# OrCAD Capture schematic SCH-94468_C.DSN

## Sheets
1 COVER PAGE: title: SCH-94468; rev: C; company: NXP Semiconductor; note: SCH-94468 PDF: SPF-94468; note: 6501 William Cannon Drive West; note: Austin, TX 78735-8598
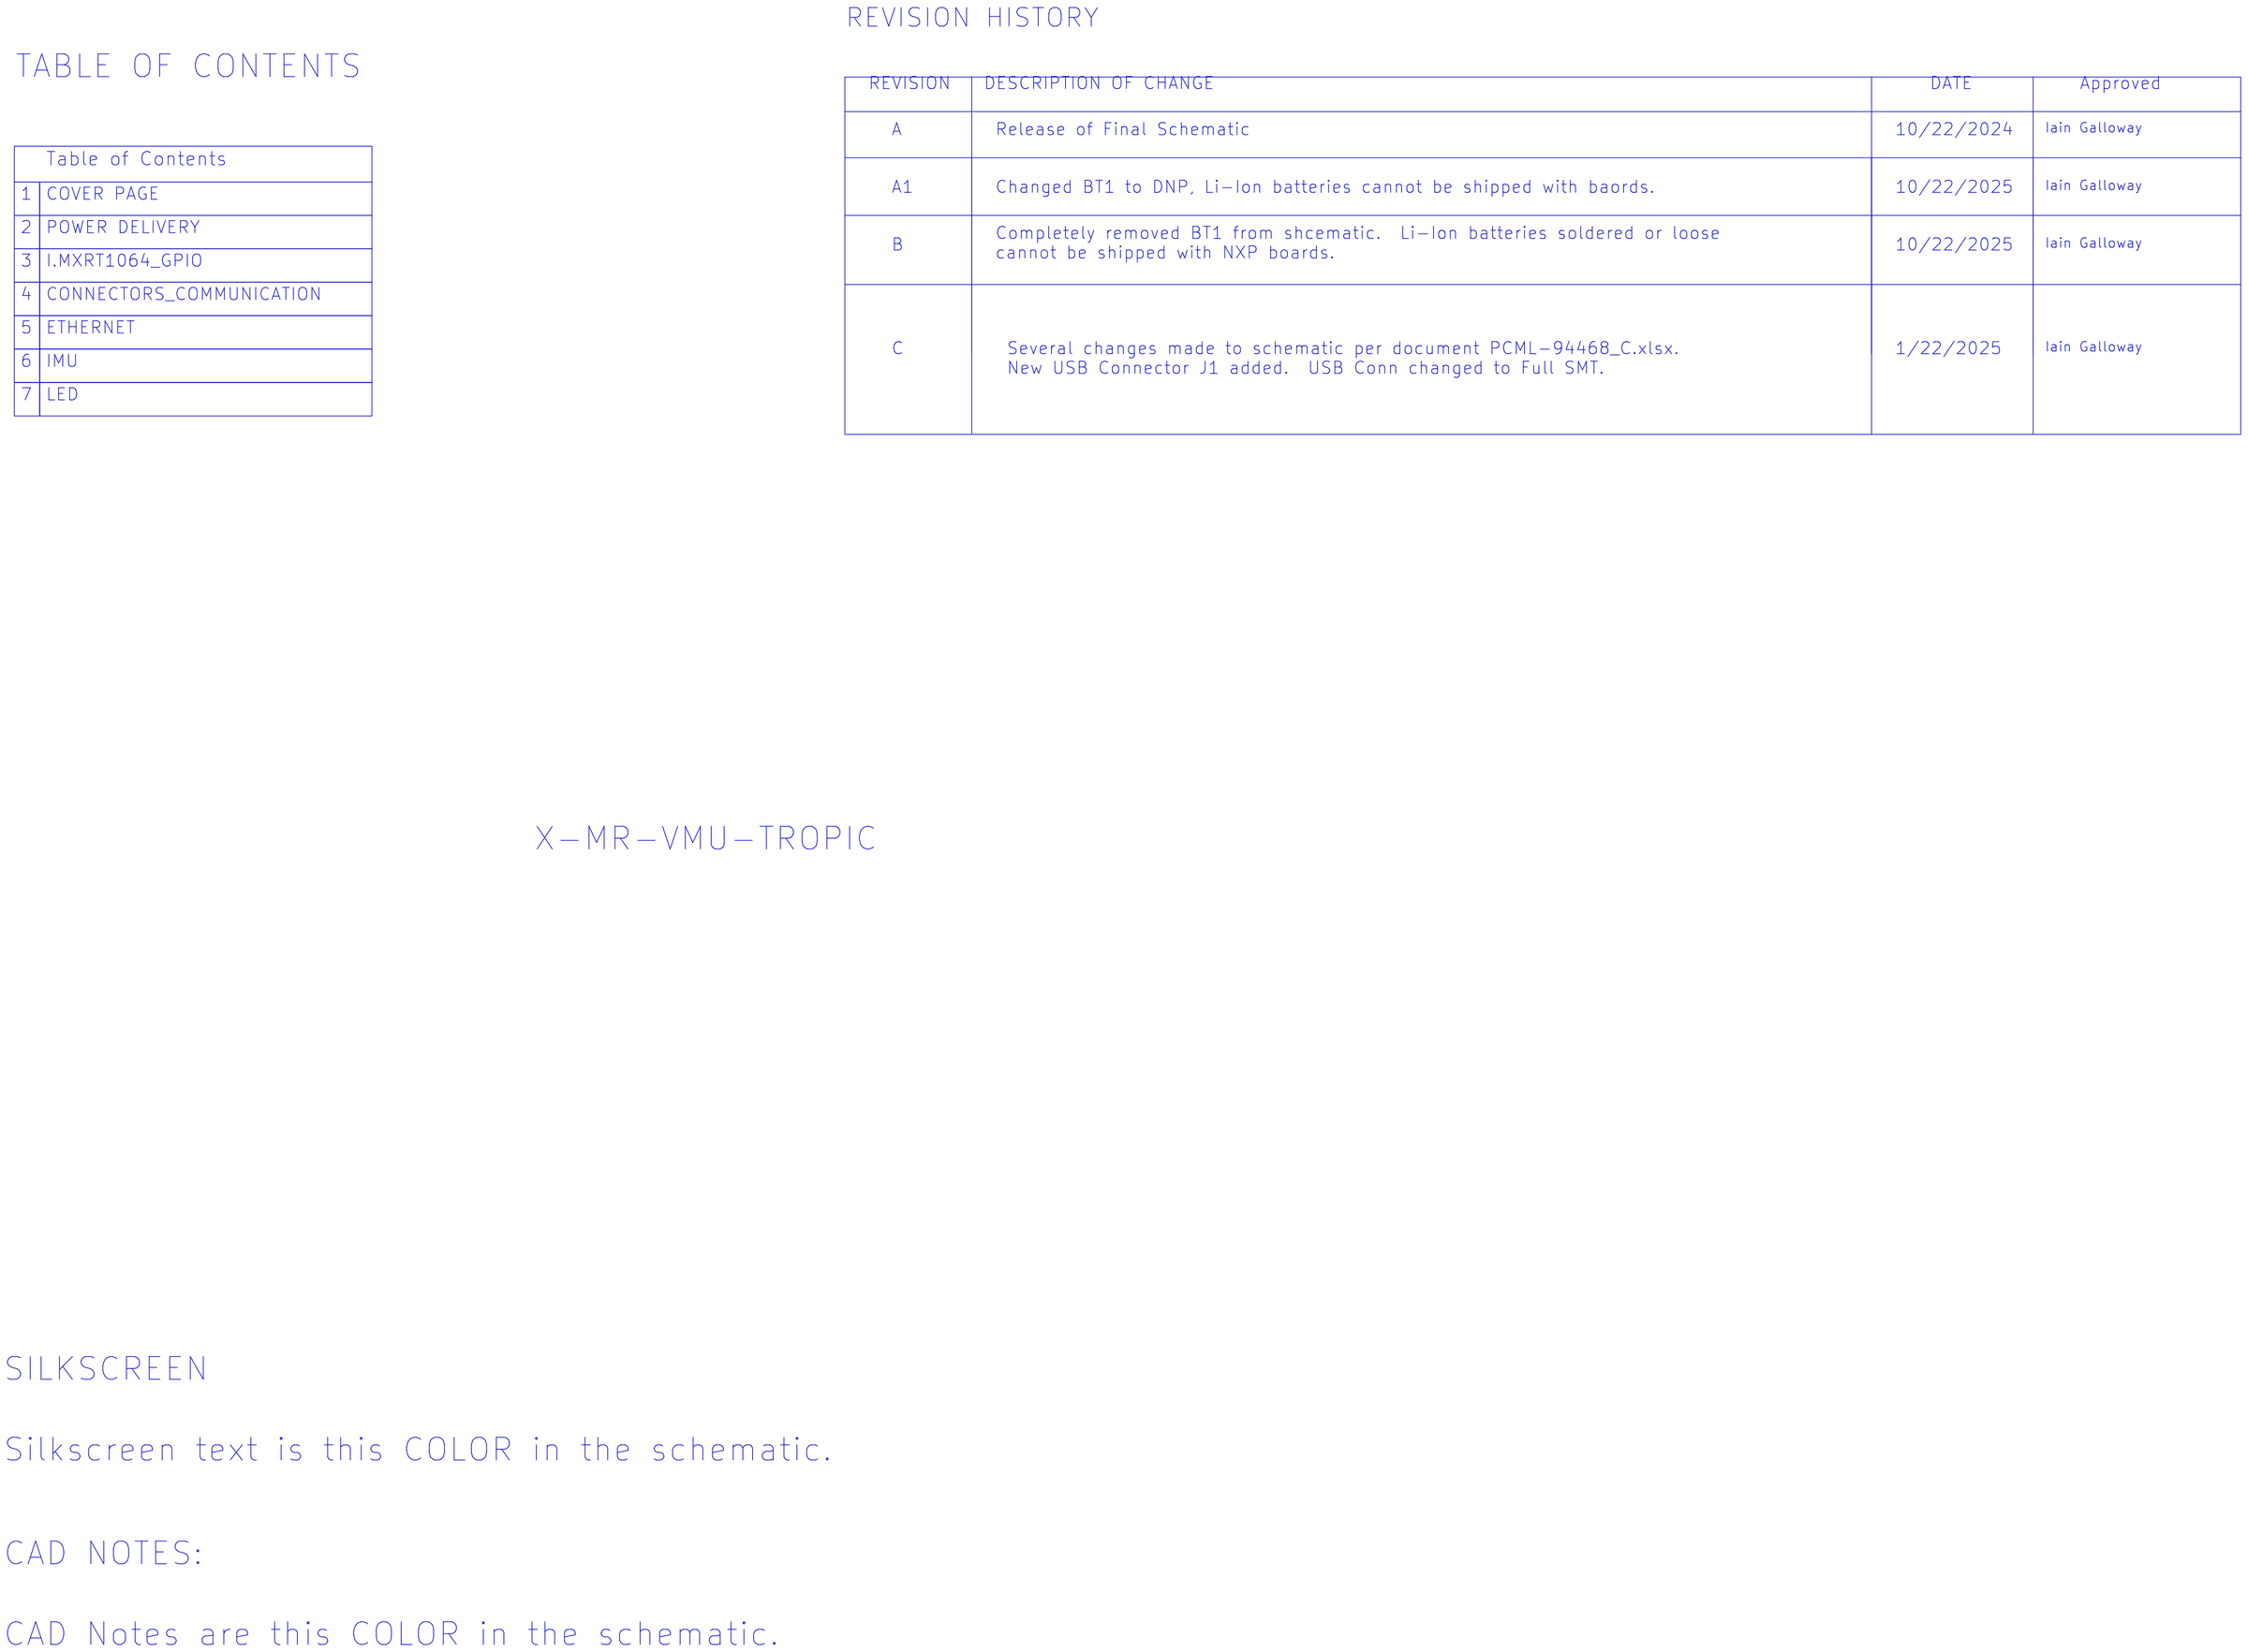
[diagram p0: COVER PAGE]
2 POWER DELIVERY: size C; company: NXP Semiconductors
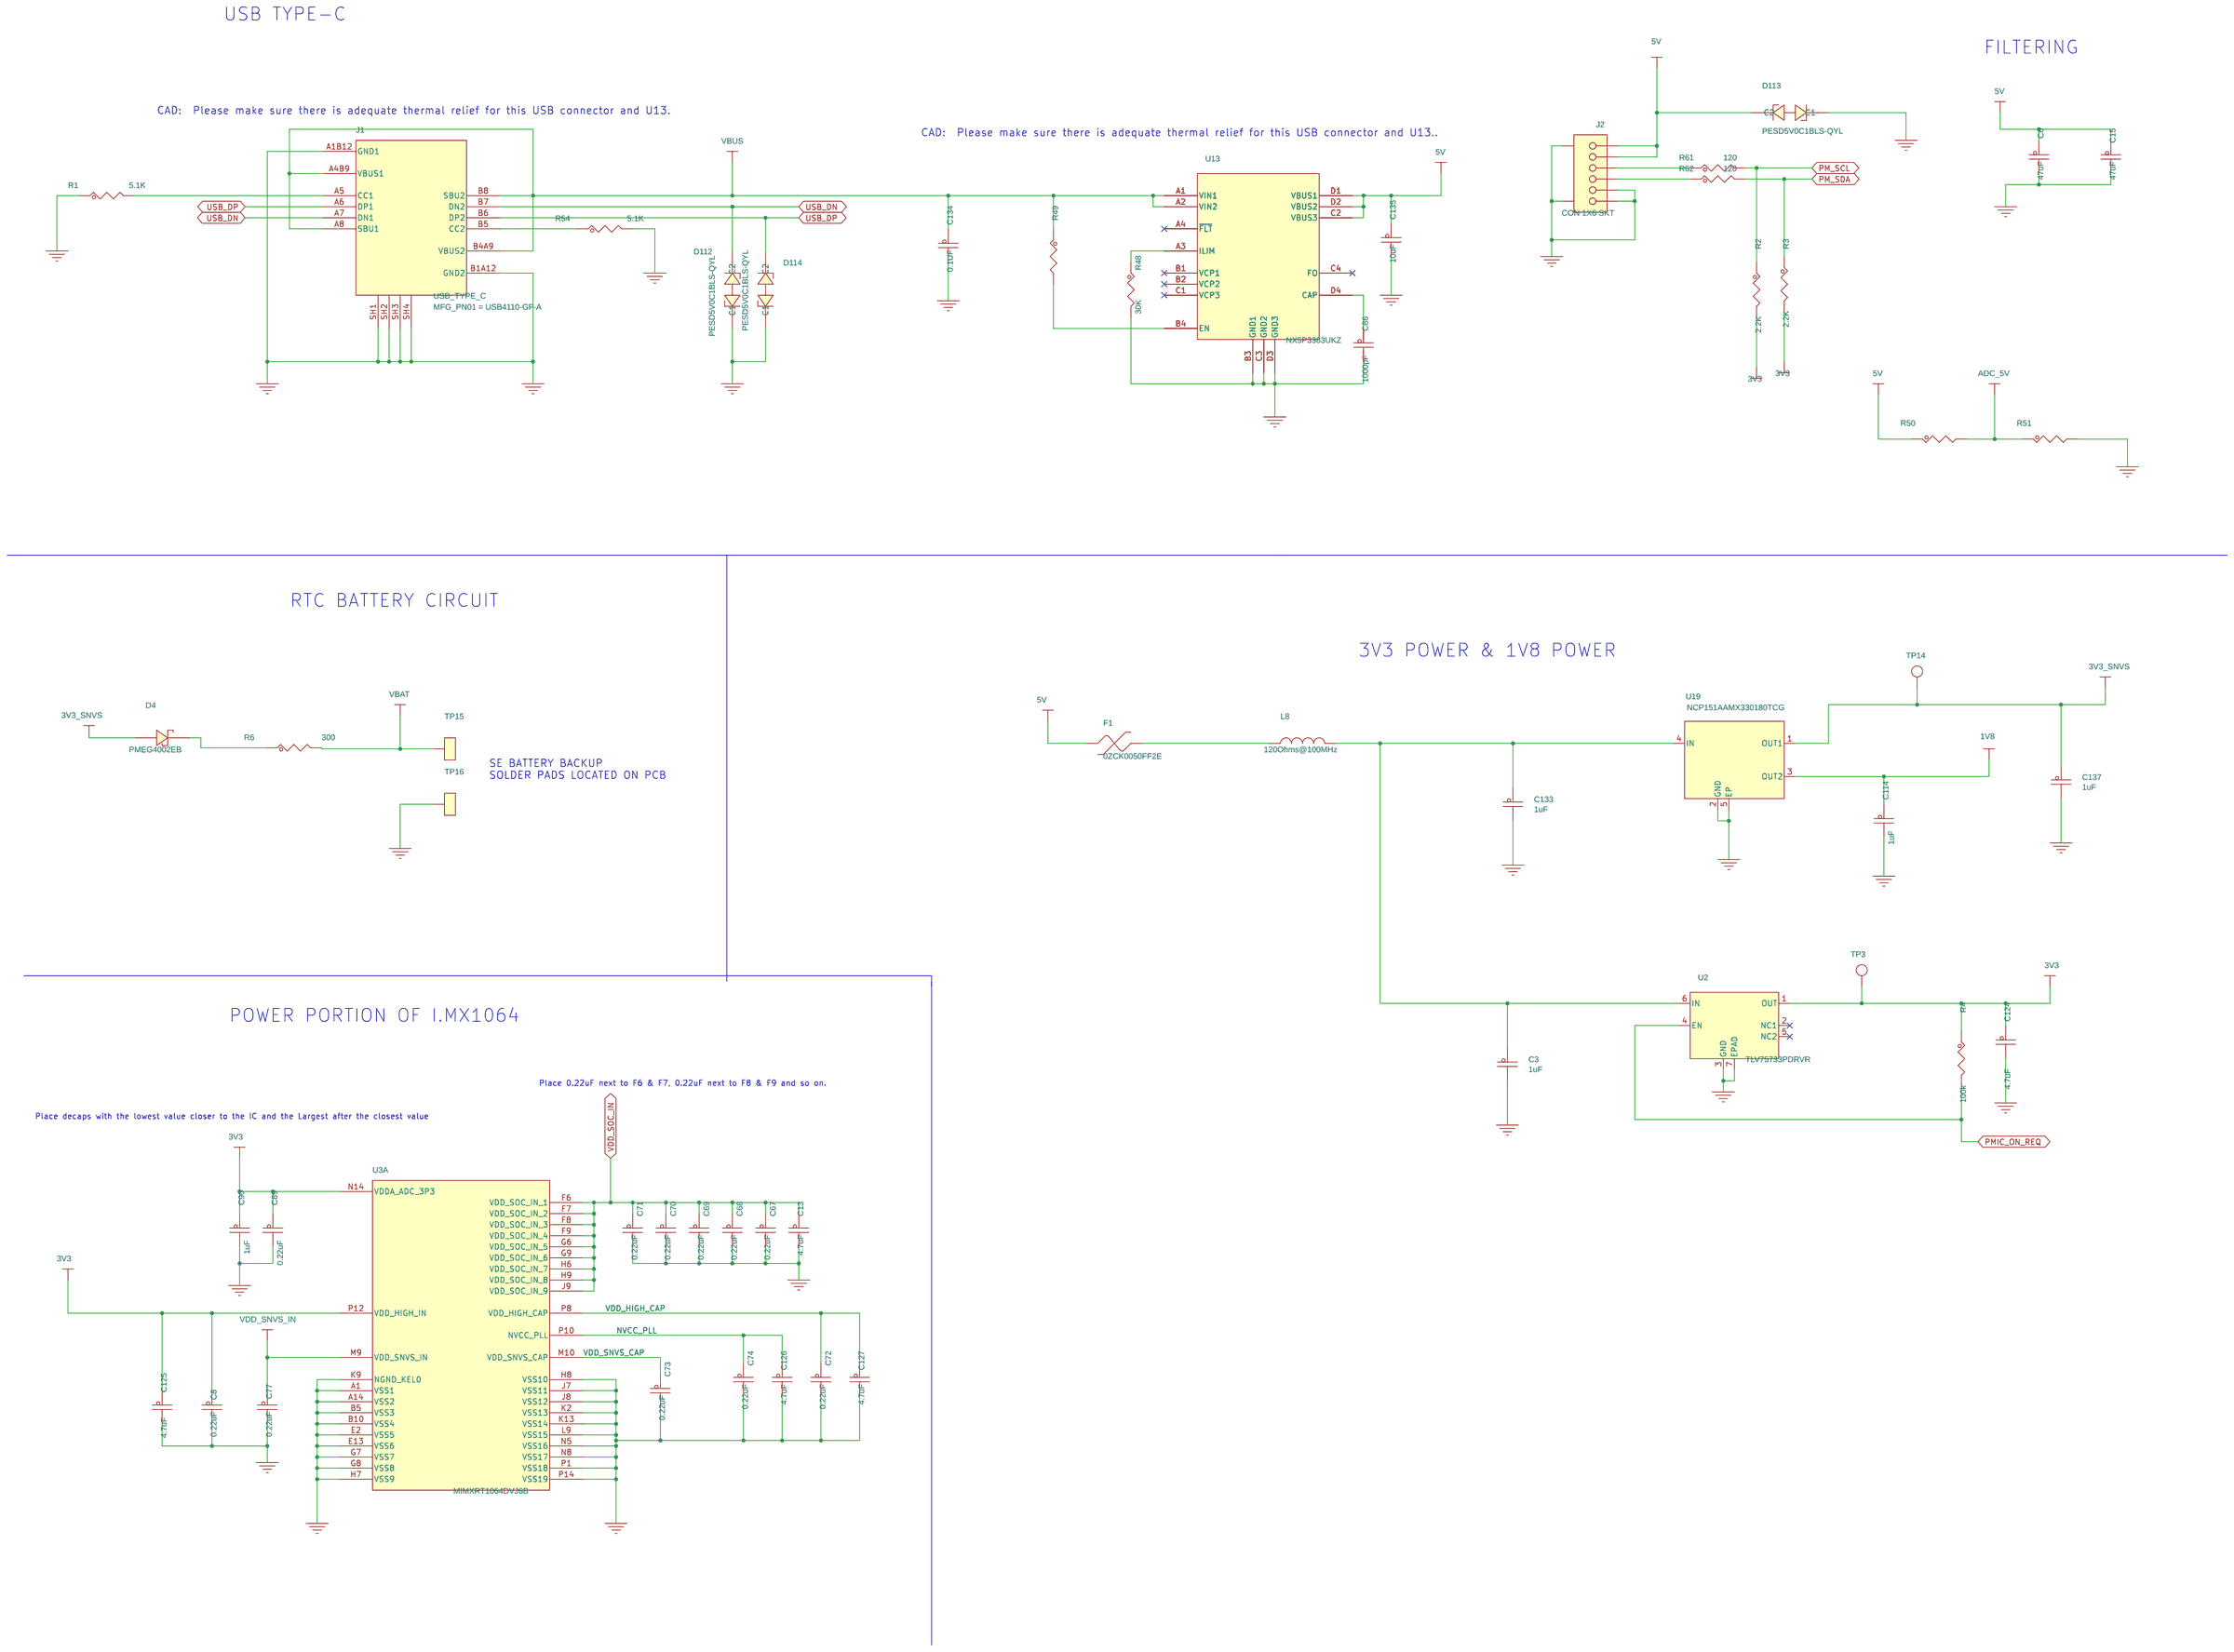
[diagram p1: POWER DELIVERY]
3 I.MXRT1064_GPIO: size D; company: NXP Semiconductors
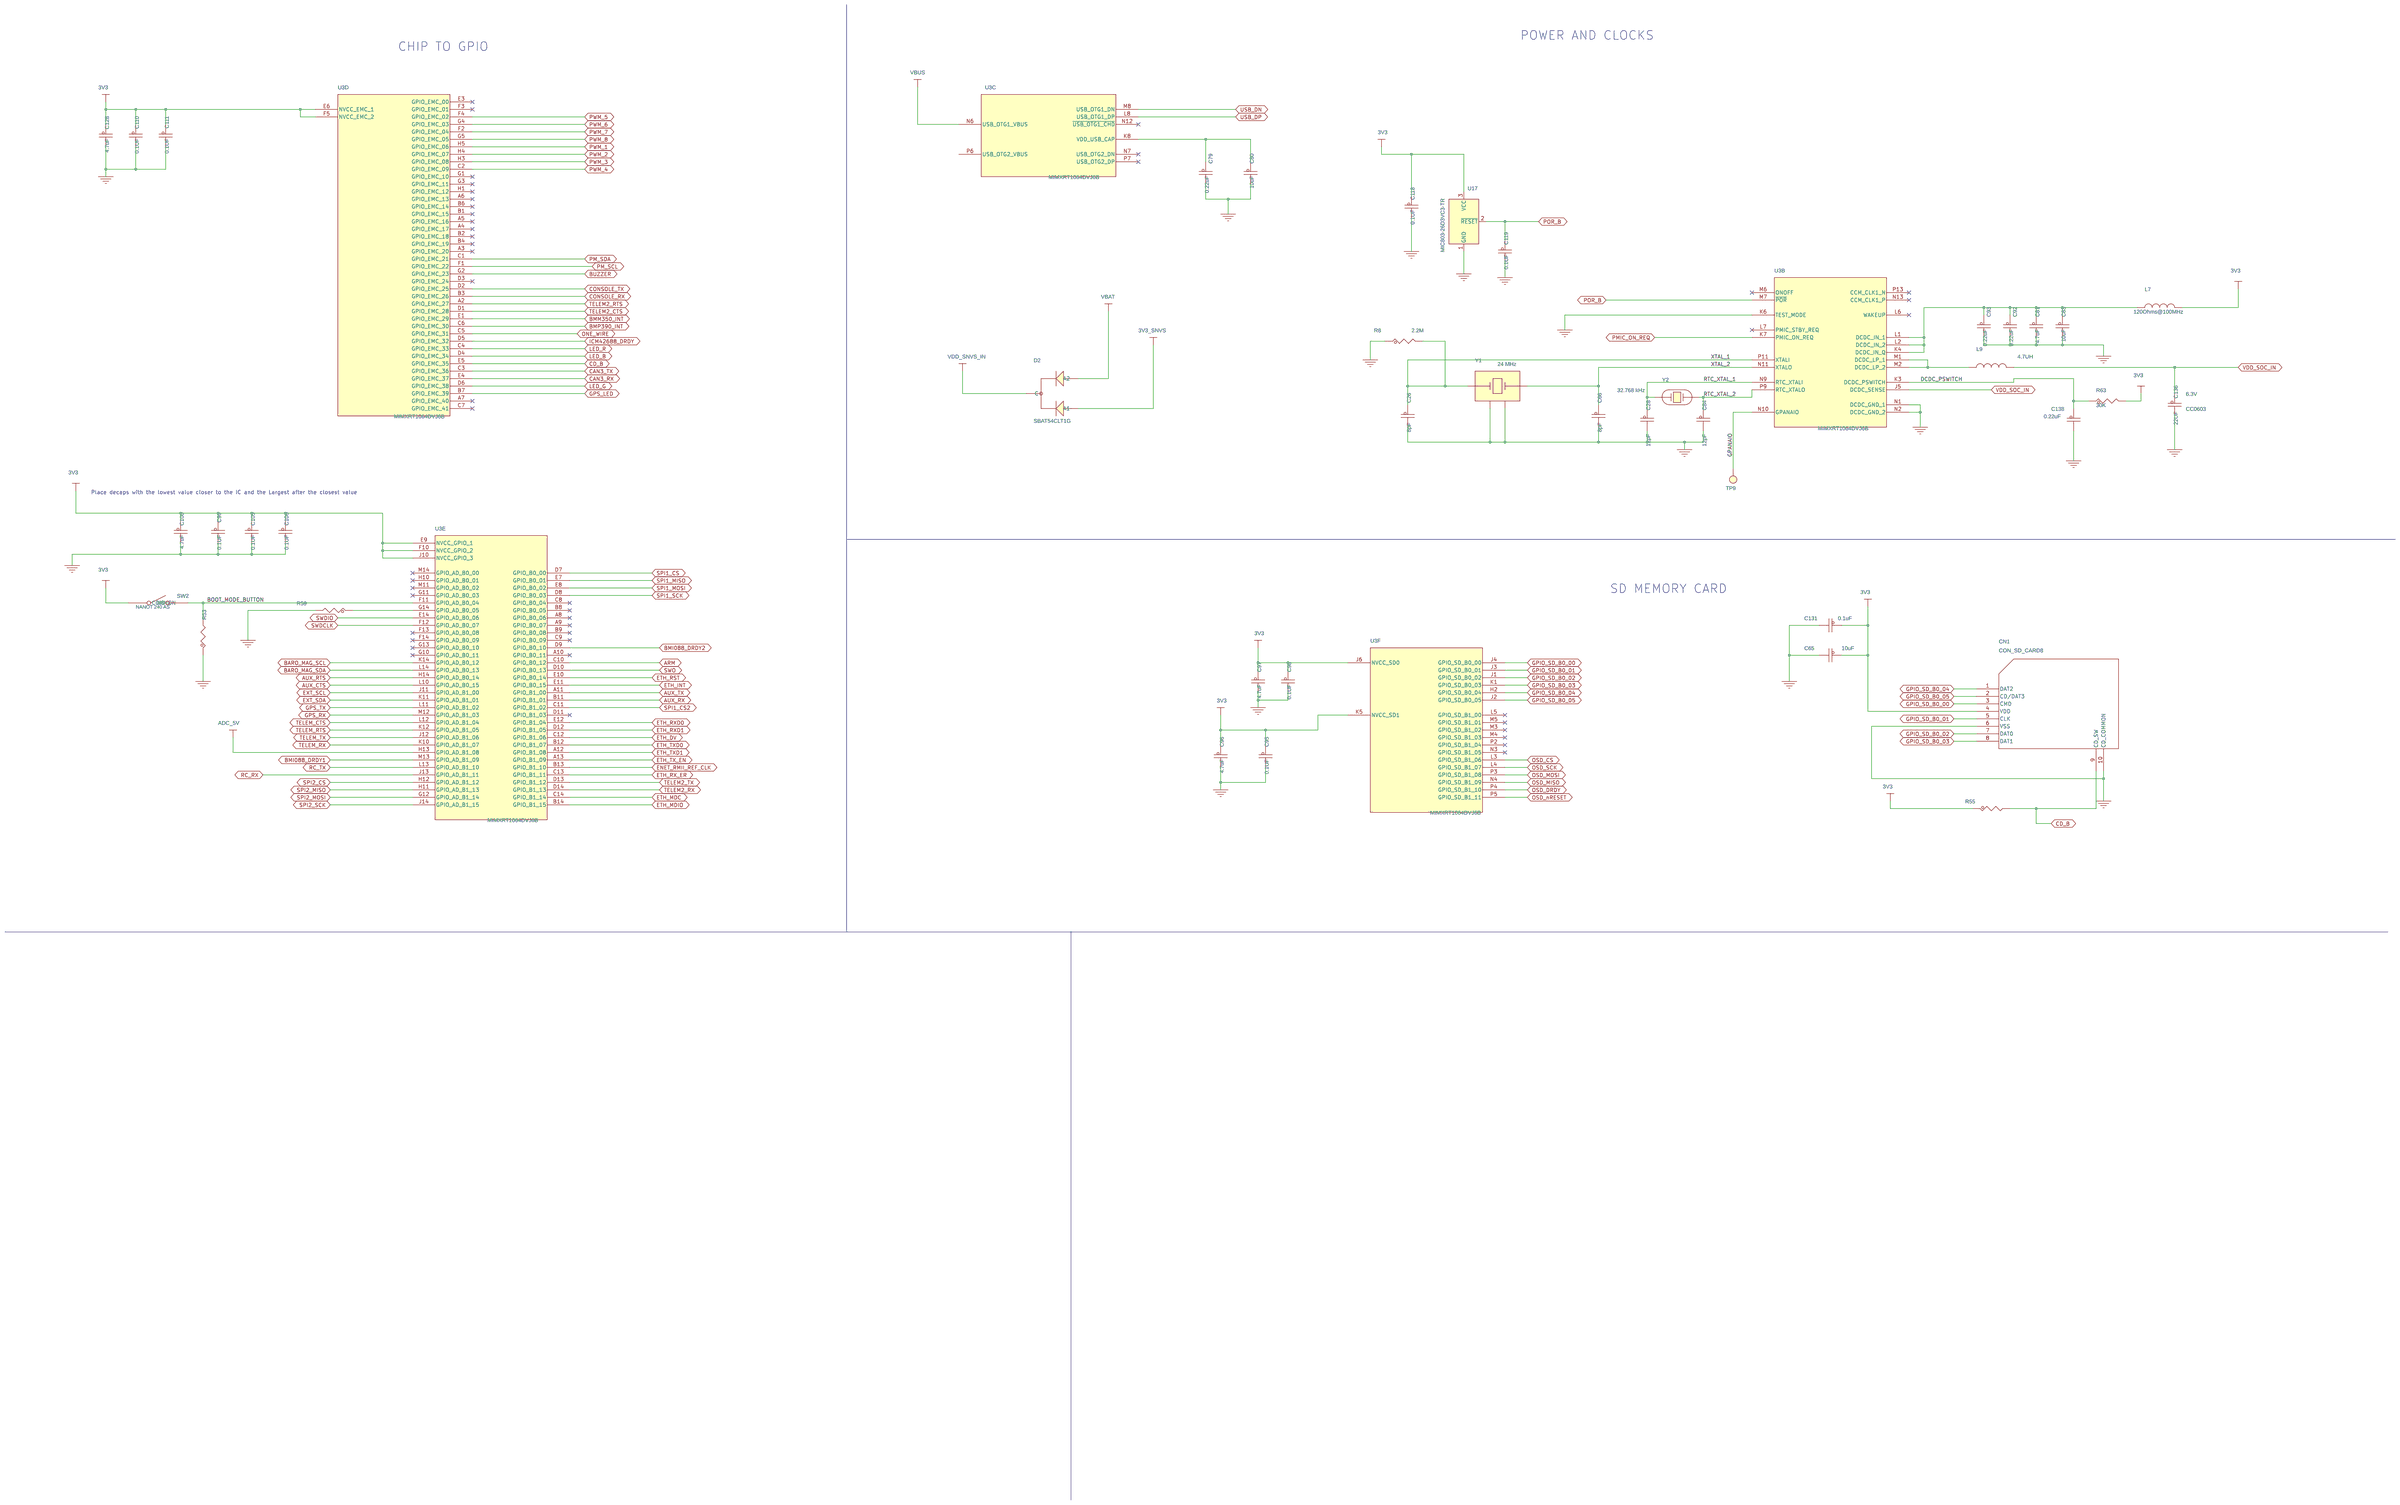
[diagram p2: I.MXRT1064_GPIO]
4 CONNECTORS_COMMUNICATION: size C; company: NXP Semiconductors
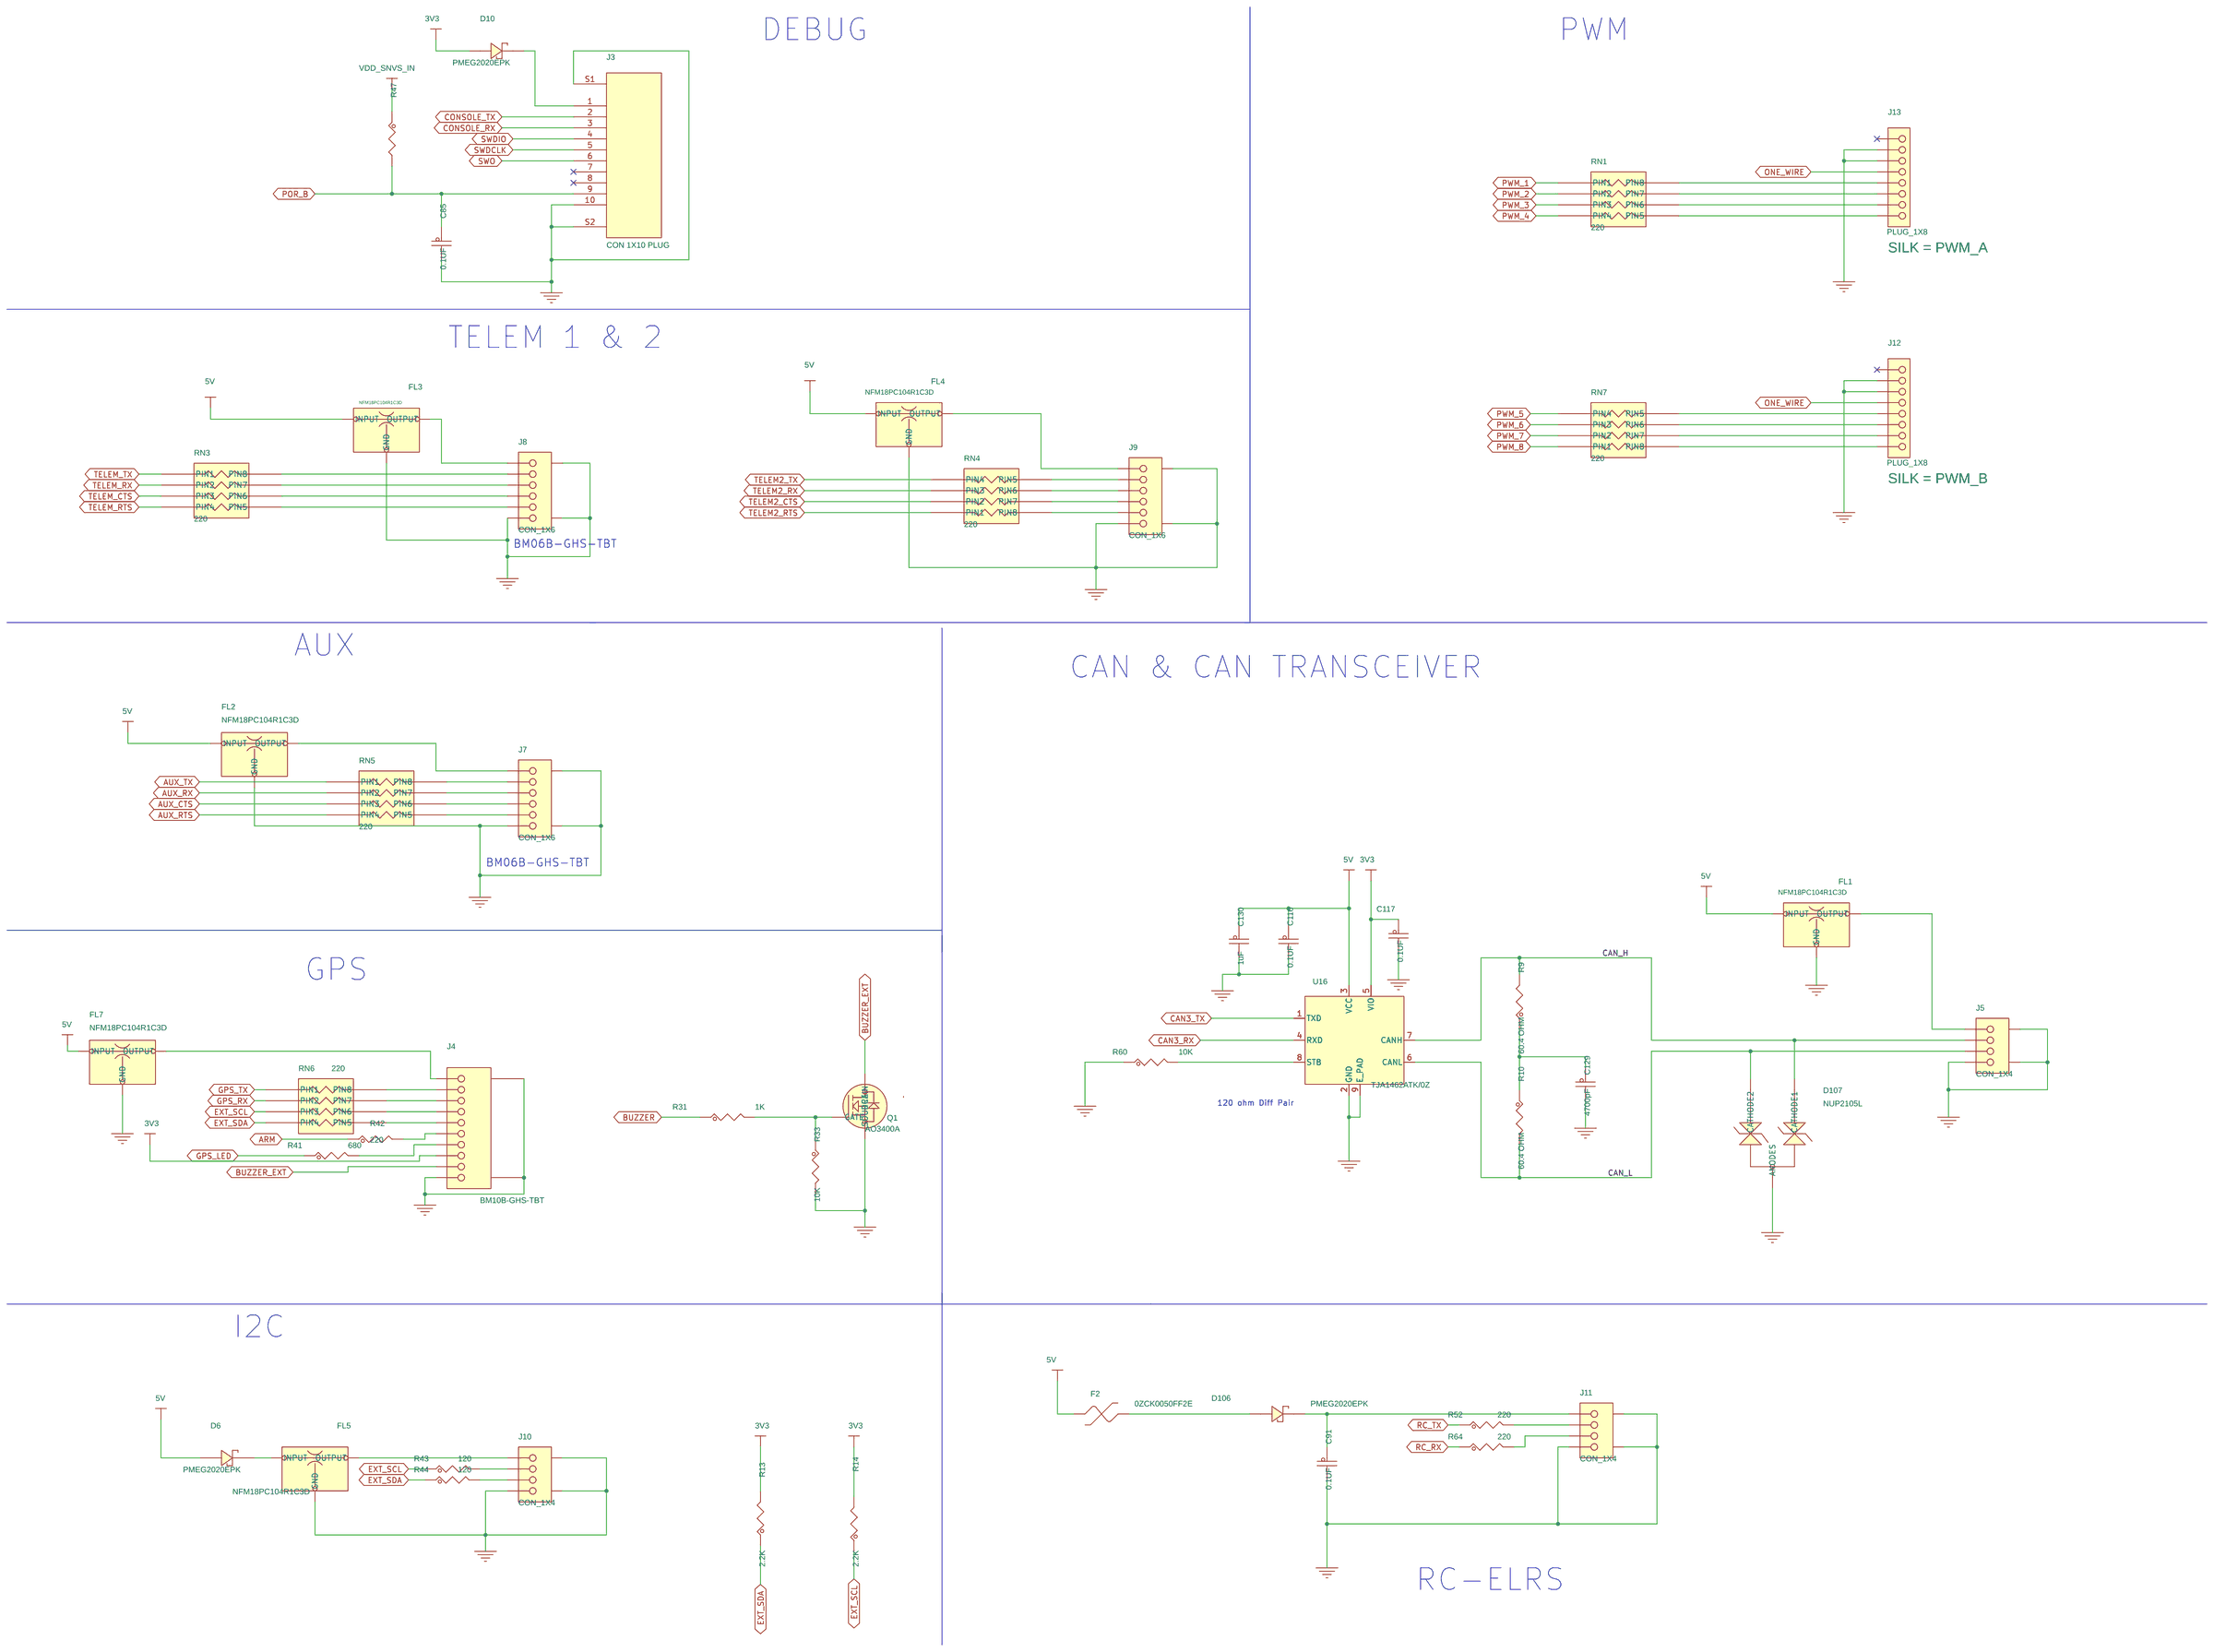
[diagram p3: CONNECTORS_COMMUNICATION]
5 ETHERNET: size C; company: NXP Semiconductors
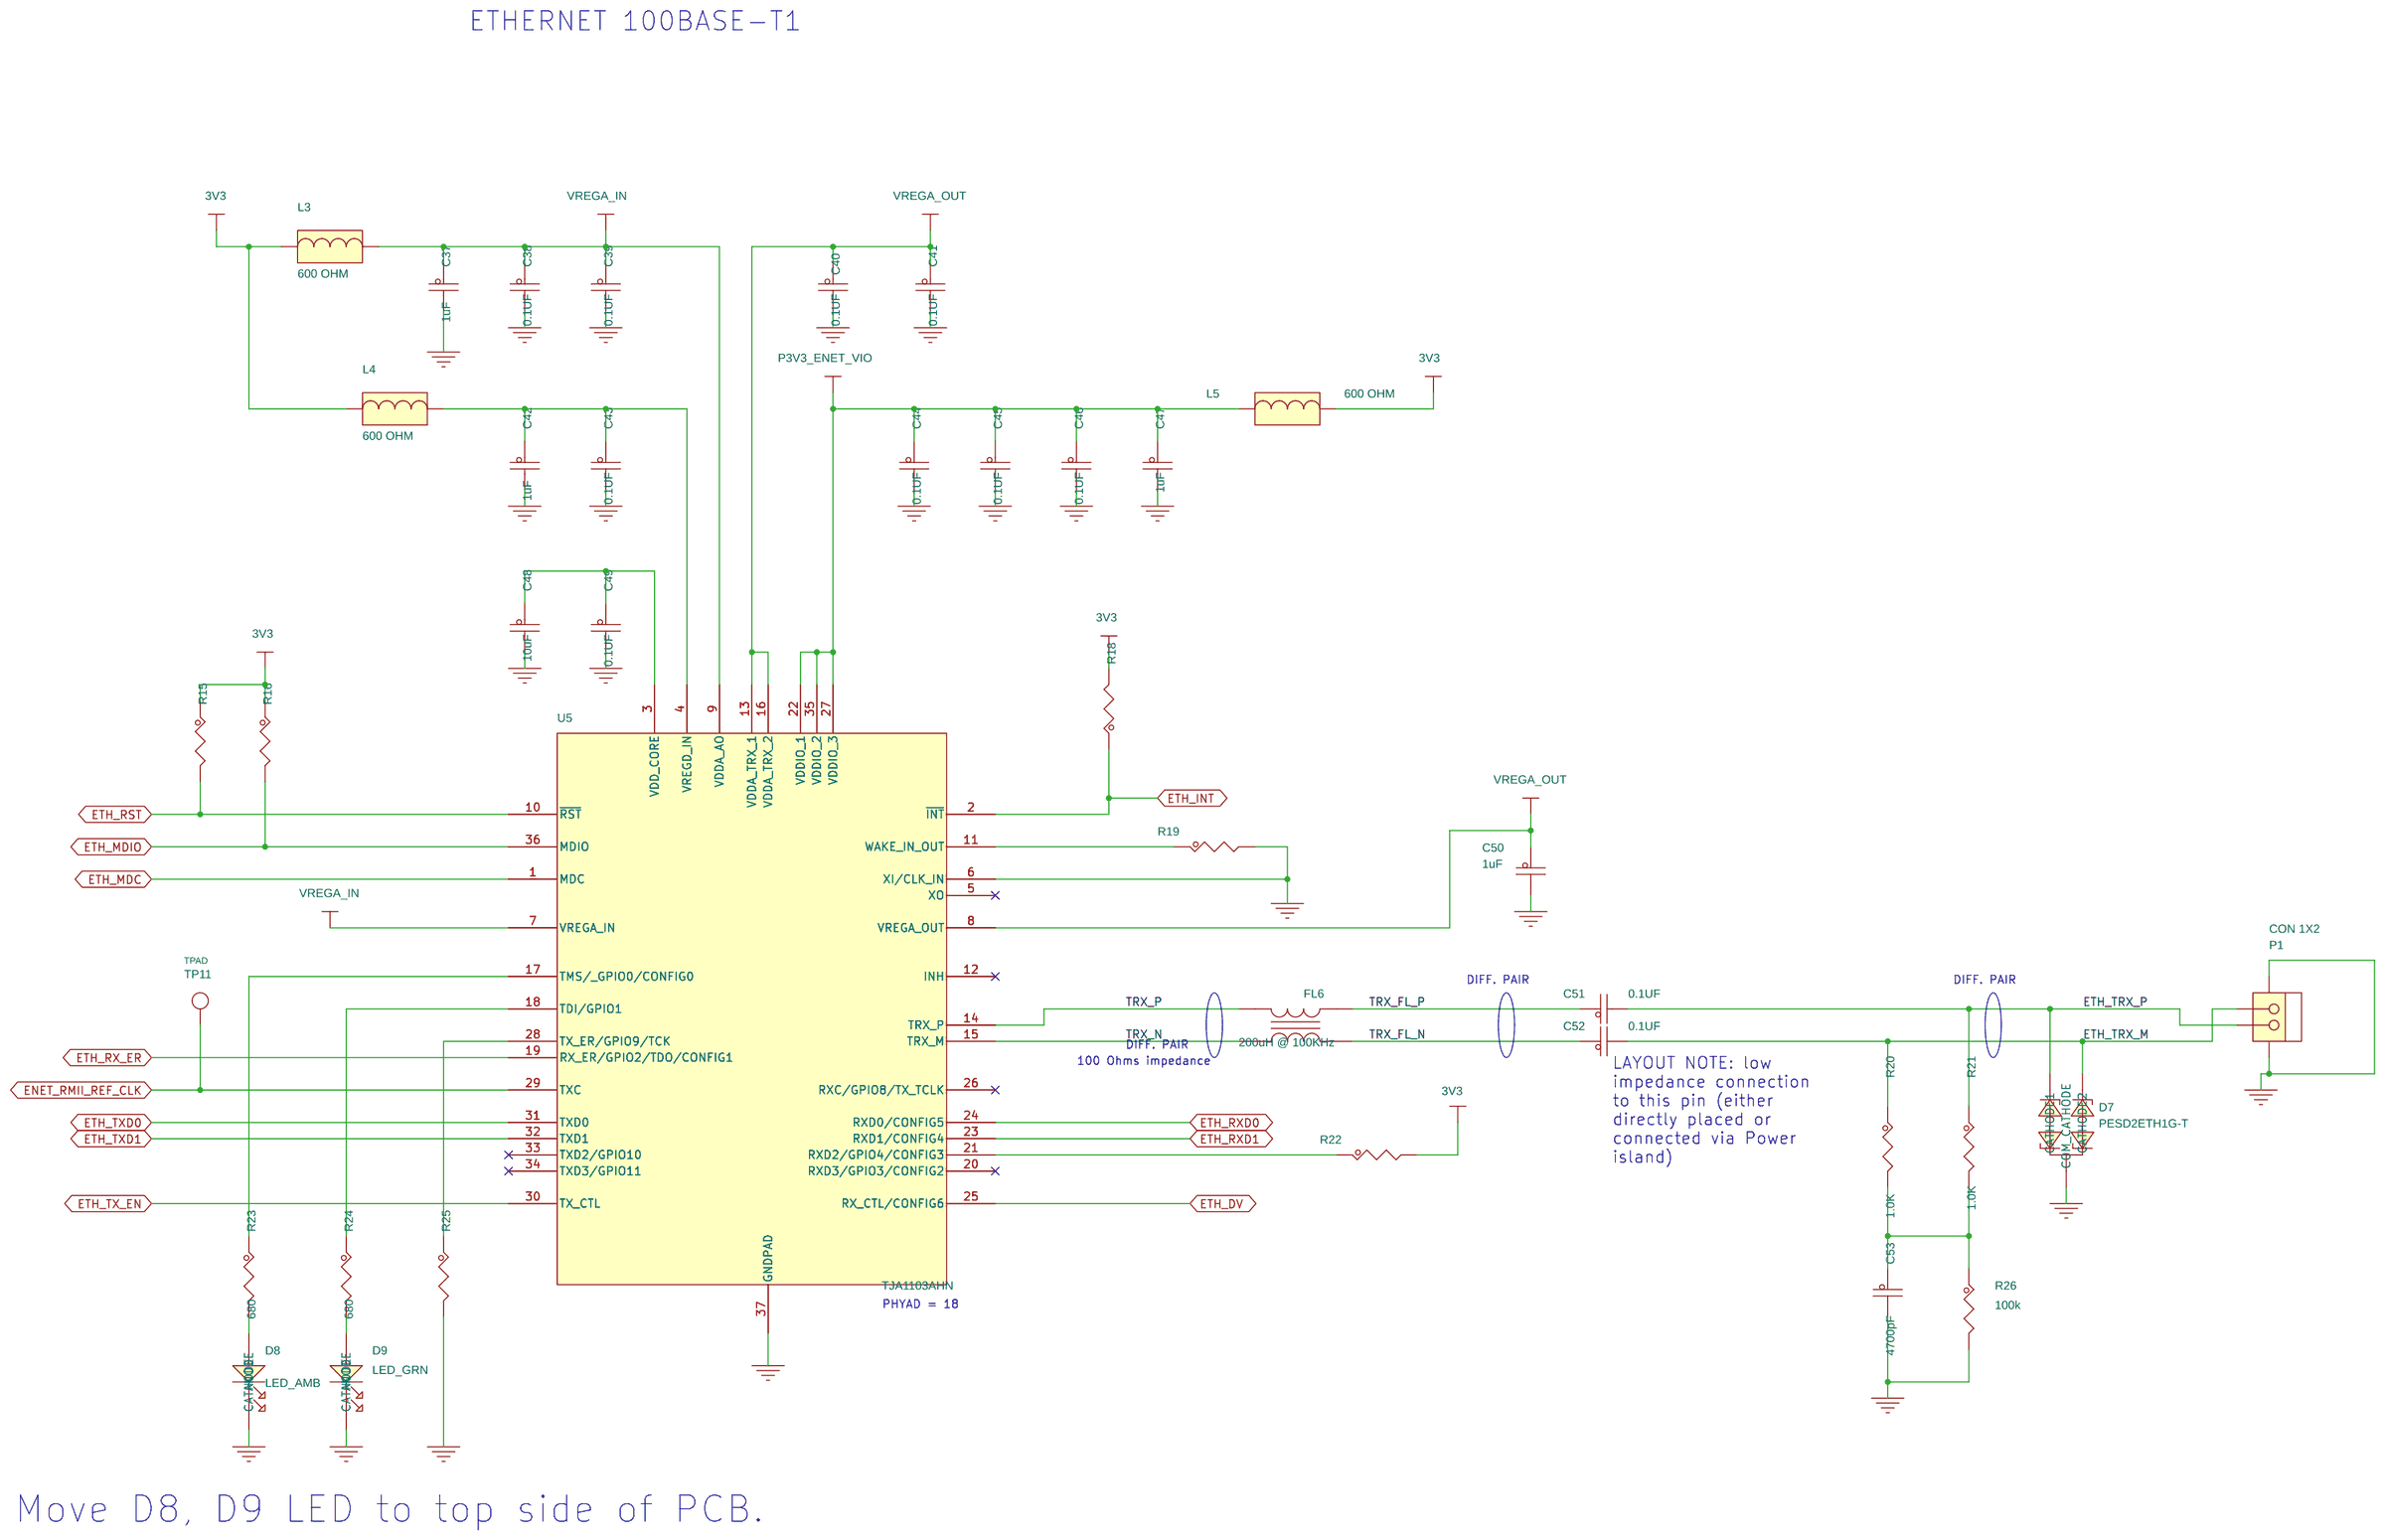
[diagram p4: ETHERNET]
6 IMU: size C; company: NXP Semiconductors
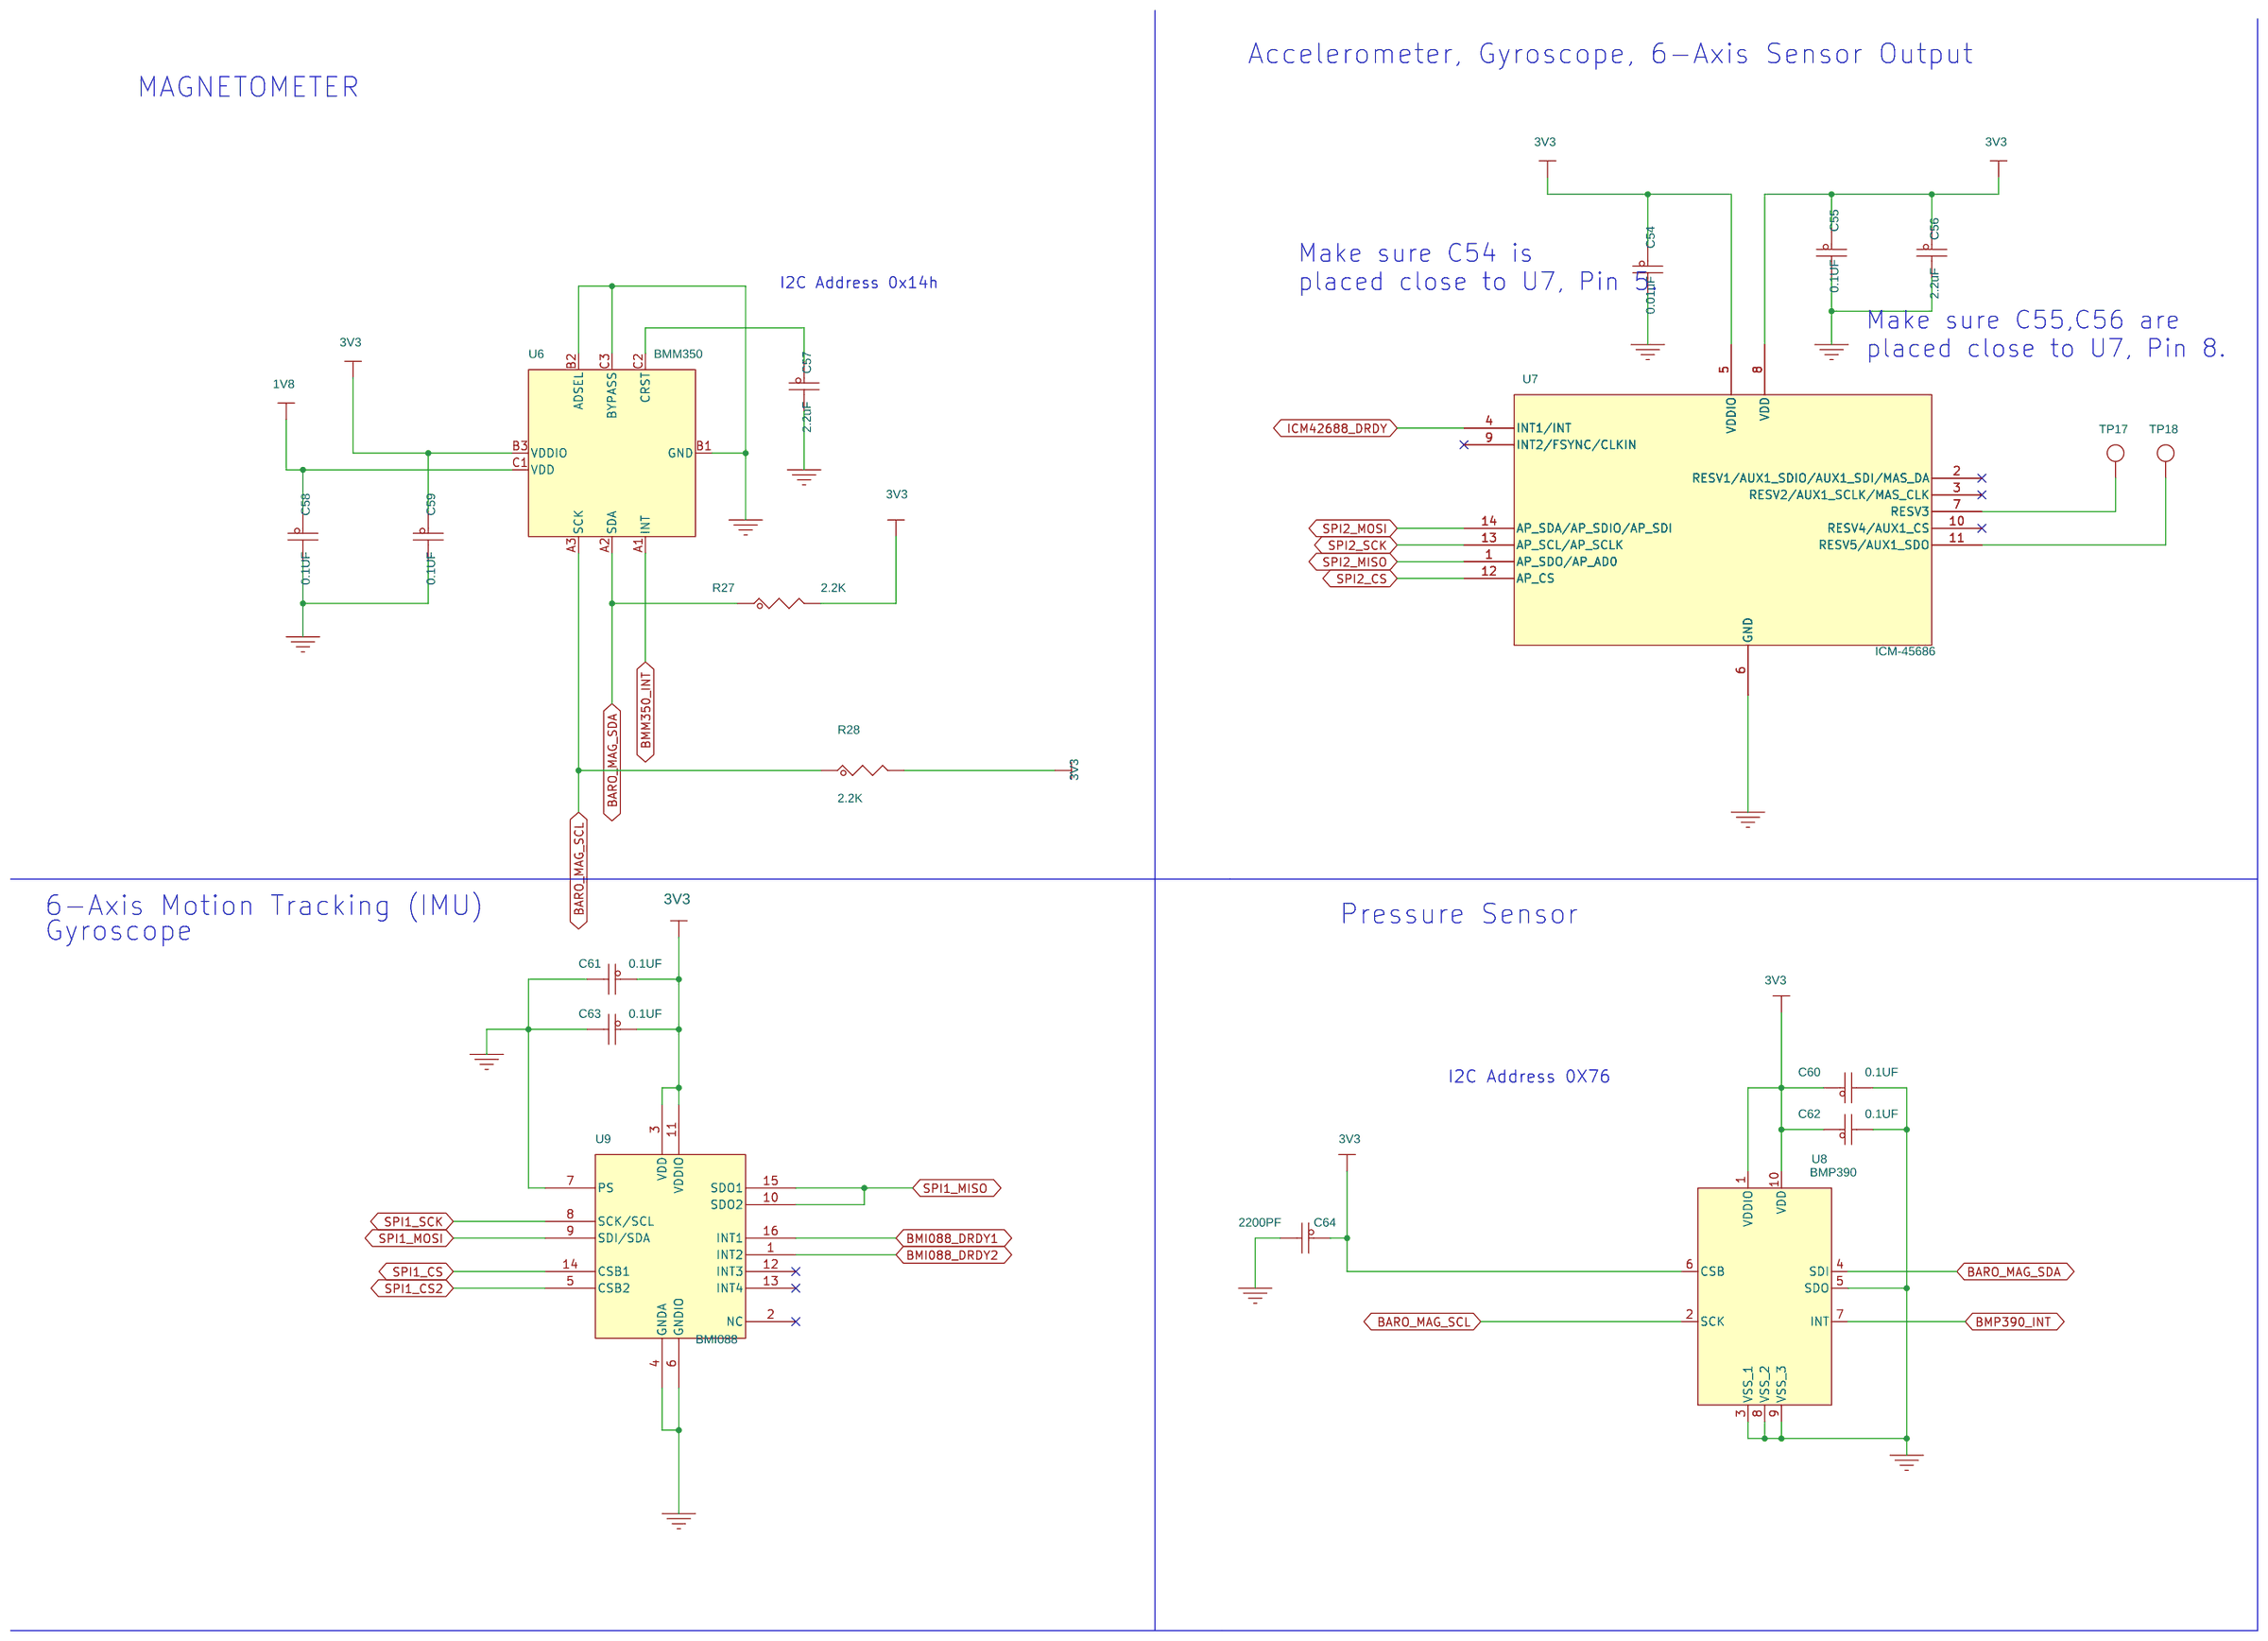
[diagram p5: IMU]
7 LED: size B; company: NXP Semiconductors
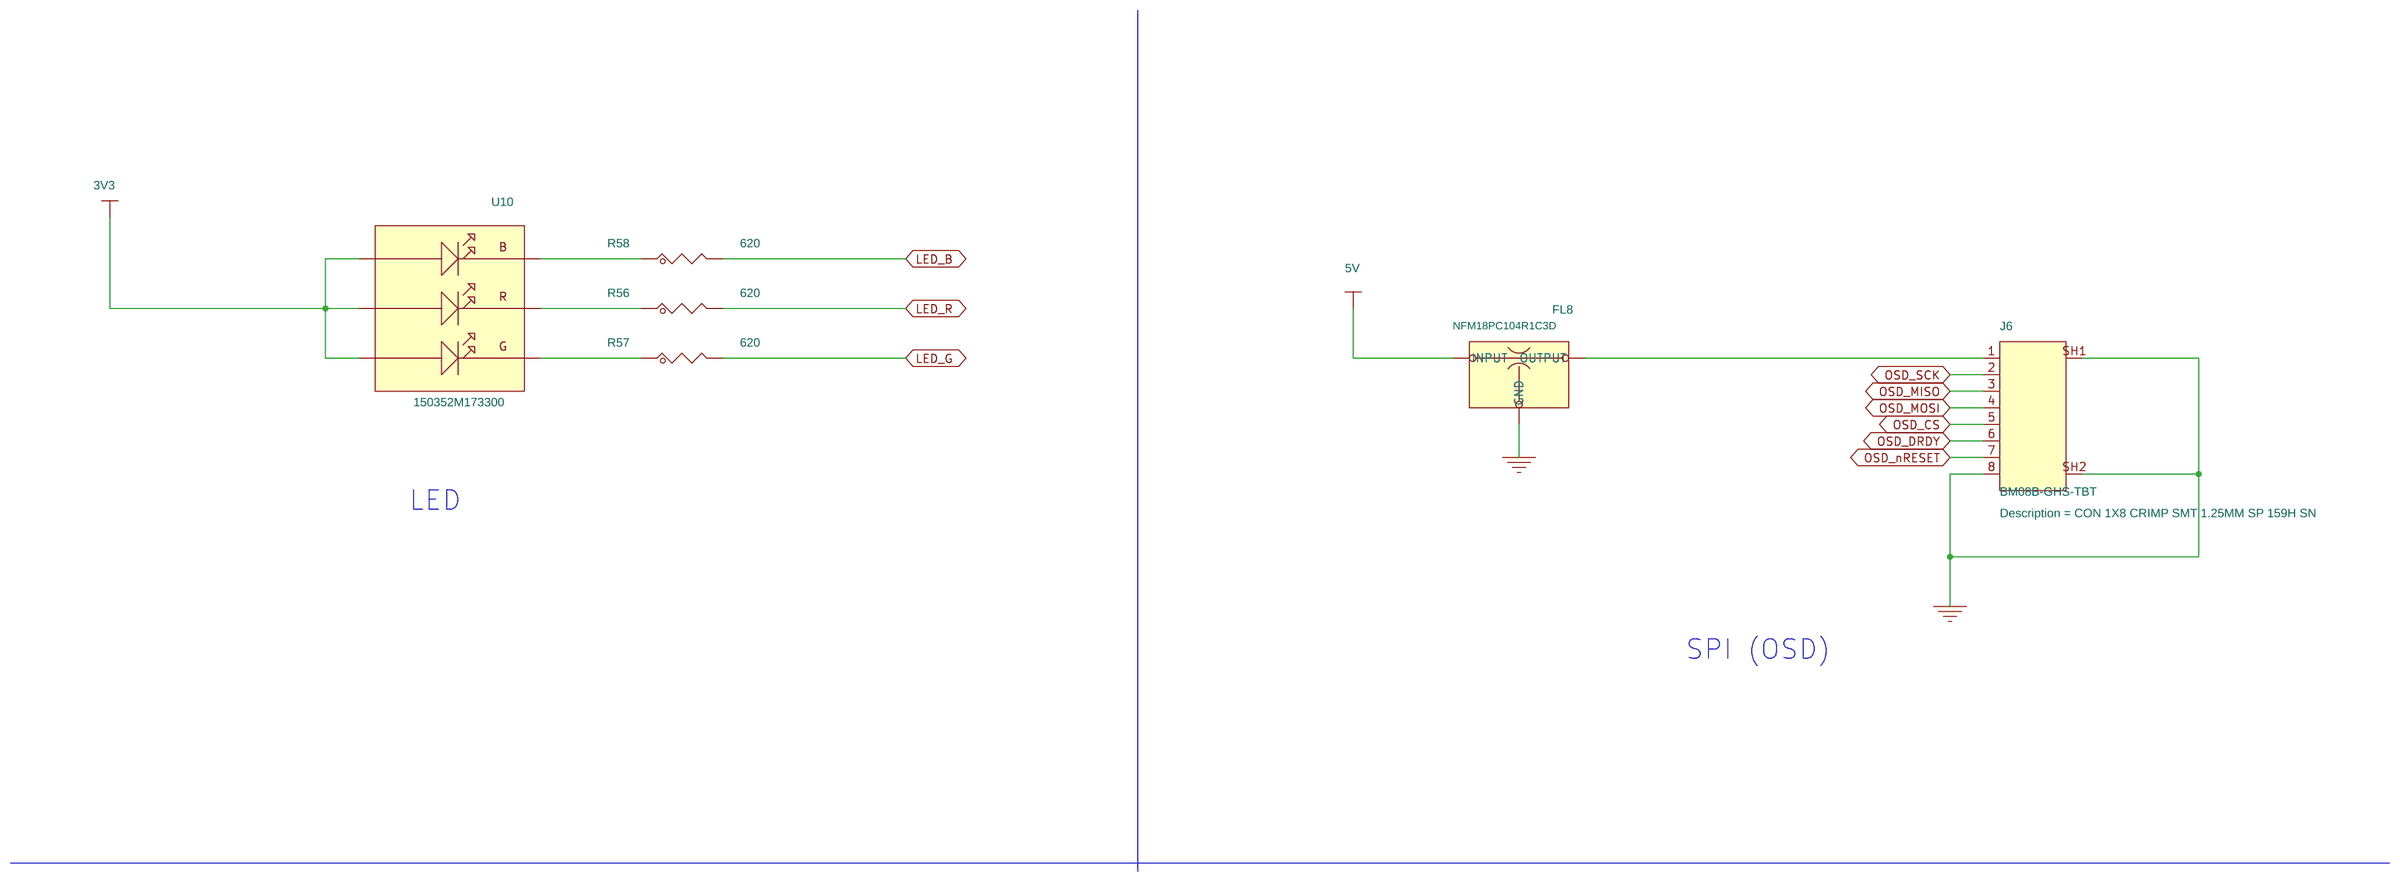
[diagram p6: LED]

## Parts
sheet CONNECTORS_COMMUNICATION
C85  0.1UF  [CC0201]
C91  0.1UF  [CC0201]
C116  0.1UF  [CC0201]
C117  0.1UF  [CC0201]
C129  4700pF  [CC0805_OV]
C130  1uF  [CC0805_OV]
D6  PMEG2020EPK  [dfn1608d-2]
D10  PMEG2020EPK  [dfn1608d-2]
D106  PMEG2020EPK  [dfn1608d-2]
D107  NUP2105L  [sot-23]
F2  0ZCK0050FF2E  [fuse_2p2x1p5_49h]
FL1  NFM18PC104R1C3D  [cc0603_nfm18pc]
FL2  NFM18PC104R1C3D  [cc0603_nfm18pc]
FL3  NFM18PC104R1C3D  [cc0603_nfm18pc]
FL4  NFM18PC104R1C3D  [cc0603_nfm18pc]
FL5  NFM18PC104R1C3D  [cc0603_nfm18pc]
FL7  NFM18PC104R1C3D  [cc0603_nfm18pc]
J3  CON 1X10 PLUG  [con_10m_1mm_sm_ra]
J4  BM10B-GHS-TBT  [con_1x10_1p25_15p75x4p25_sm]
J5  CON_1X4  [con_1x4_1p25_8p25x4p25_sm]
J7  CON_1X6  [con_1x6_1p25_10p75x4p25_sm]
J8  CON_1X6  [con_1x6_1p25_10p75x4p25_sm]
J9  CON_1X6  [con_1x6_1p25_10p75x4p25_sm]
J10  CON_1X4  [con_1x4_1p25_8p25x4p25_sm]
J11  CON_1X4  [con_1x4_1p25_8p25x4p25_sm]
J12  PLUG_1X8  [plug1x8_1mm_shrd_sm]
J13  PLUG_1X8  [plug1x8_1mm_shrd_sm]
Q1  AO3400A  [sot-23w]
R9  60.4 OHM  [RC0402_25]
R10  60.4 OHM  [RC0402_25]
R13  2.2K  [RC0402_25]
R14  2.2K  [RC0402_25]
R31  1K  [rc0402_25]
R33  10K  [RC0402_25]
R41  680  [RC0402_25]
R42  220  [RC0402_25]
R43  120  [RC0402_25]
R44  120  [RC0402_25]
R47  10K  [RC0402_25]
R52  220  [RC0402_25]
R60  10K  [RC0402_25]
R64  220  [RC0402_25]
RN1  220  [rnet_38v_0603]
RN3  220  [rnet_38v_0603]
RN4  220  [rnet_38v_0603]
RN5  220  [rnet_38v_0603]
RN6  220  [rnet_38v_0603]
RN7  220  [rnet_38v_0603]
U16  TJA1462ATK/0Z  [son8_0p65_3p15x3p15]
sheet ETHERNET
C37  1uF  [CC0402_25]
C38  0.1UF  [CC0201]
C39  0.1UF  [CC0201]
C40  0.1UF  [CC0201]
C41  0.1UF  [CC0201]
C42  1uF  [CC0402_25]
C43  0.1UF  [CC0201]
C44  0.1UF  [CC0201]
C45  0.1UF  [CC0201]
C46  0.1UF  [CC0201]
C47  1uF  [CC0402_25]
C48  10uF  [cc0402_tol0p2]
C49  0.1UF  [CC0201]
C50  1uF  [CC0402_25]
C51  0.1UF  [CC0201]
C52  0.1UF  [CC0201]
C53  4700pF  [CC0402_25]
D7  PESD2ETH1G-T  [sot23_a]
D8  LED_AMB  [LED_0603]
D9  LED_GRN  [LED_0603]
FL6  200uH @ 100KHz  [ind_act1210_sm]
L3  600 OHM  [IND_0603]
L4  600 OHM  [IND_0603]
L5  600 OHM  [IND_0603]
P1  CON 1X2  [con_1x2_1p25_5p75x4p25_sm]
R15  10K  [RC0402_25]
R16  10K  [RC0402_25]
R18  10K  [RC0402_25]
R19  10K  [RC0402_25]
R20  1.0K  [RC0805_OV]
R21  1.0K  [RC0805_OV]
R22  10K  [RC0402_25]
R23  680  [RC0402_25]
R24  680  [RC0402_25]
R25  10K  [RC0402_25]
R26  100k  [RC0402_25]
TP11  TPAD_030  [TPAD_030]
U5  TJA1103AHN  [qfn36_0p5_6x6]
sheet I.MXRT1064_GPIO
C26  8pF  [CC0402_25]
C28  12pF  [CC0402_25]
C65  10uF  [CC0603_OV]
C66  8pF  [CC0402_25]
C79  0.22uF  [CC0201]
C80  10uF  [cc0402_tol0p2]
C81  4.7uF  [cc0402_tol0p2]
C83  10uF  [cc0402_tol0p2]
C84  12pF  [CC0402_25]
C92  0.22uF  [CC0201]
C93  0.22uF  [CC0201]
C95  0.1UF  [CC0201]
C96  4.7uF  [cc0402_tol0p2]
C97  4.7uF  [cc0402_tol0p2]
C98  0.1UF  [CC0201]
C99  0.1UF  [CC0201]
C100  4.7uF  [cc0402_tol0p2]
C105  0.1UF  [CC0201]
C106  0.1UF  [CC0201]
C110  0.1UF  [CC0201]
C111  0.1UF  [CC0201]
C118  0.1UF  [CC0201]
C119  0.1UF  [CC0201]
C128  4.7uF  [cc0402_tol0p2]
C131  0.1uF  [CC0201]
C136  22UF  [CC0603]
C138  0.22uF  [CC0201]
CN1  CON_SD_CARD8  [con8_microsdcard_1p1mm_sm]
D2  SBAT54CLT1G  [sot23_a]
L7  120Ohms@100MHz  [IND_0402]
L9  4.7UH  [ind_1008_smd]
R8  2.2M  [RC0402_25]
R53  10K  [RC0402_25]
R55  10K  [RC0402_25]
R59  10K  [RC0402_25]
R63  30K  [RC0402_25]
SW2  NANOT 240 AS  [sw2_tact_2p1x1p65_sm]
TP9  TP_35MIL  [testpoint_35mil]
U17  MIC803-26D3VC3-TR  [sc70_3]
Y1  24 MHz  [xtal4_cx3225ca_sm]
Y2  32.768 kHz  [xtal2_2p1x1p3_sm]
sheet IMU
C54  0.01uF  [CC0201]
C55  0.1UF  [CC0201]
C56  2.2uF  [cc0402_tol0p15]
C57  2.2uF  [cc0402_tol0p15]
C58  0.1UF  [CC0201]
C59  0.1UF  [CC0201]
C60  0.1UF  [CC0201]
C61  0.1UF  [CC0201]
C62  0.1UF  [CC0201]
C63  0.1UF  [CC0201]
C64  2200PF  [CC0201]
R27  2.2K  [RC0402_25]
R28  2.2K  [RC0402_25]
TP17  TPAD_030  [TPAD_030]
TP18  TPAD_030  [TPAD_030]
U6  BMM350  [wlcsp9_0p4_1p28sq]
U7  ICM-45686  [lga14_0p5_3x2p5]
U8  BMP390  [lga10_0p5_2x2]
U9  BMI088  [lga16_0p5_3x4p5mm]
sheet LED
FL8  NFM18PC104R1C3D  [cc0603_nfm18pc]
J6  BM08B-GHS-TBT  [con_1x8_1p25_13p25x4p25_sm]
R56  620  [RC0402_25]
R57  620  [RC0402_25]
R58  620  [RC0402_25]
U10  150352M173300  [led6_0p85_3p25x2p85_sm]
sheet POWER DELIVERY
C3  1uF  [CC0805_OV]
C6  47uF  [CC1210]
C8  0.22uF  [CC0201]
C13  4.7uF  [cc0402_tol0p2]
C15  47uF  [CC1210]
C67  0.22uF  [CC0201]
C68  0.22uF  [CC0201]
C69  0.22uF  [CC0201]
C70  0.22uF  [CC0201]
C71  0.22uF  [CC0201]
C72  0.22uF  [CC0201]
C73  0.22uF  [CC0201]
C74  0.22uF  [CC0201]
C77  0.22uF  [CC0201]
C86  1000pF  [CC0402_25]
C89  0.22uF  [CC0201]
C90  1uF  [0402_CC]
C114  1uF  [CC0402_25]
C124  4.7uF  [cc0402_tol0p2]
C125  4.7uF  [cc0402_tol0p2]
C126  4.7uF  [cc0402_tol0p2]
C127  4.7uF  [cc0402_tol0p2]
C133  1uF  [CC0805_OV]
C134  0.1UF  [CC0201]
C135  10uF  [cc0402_tol0p2]
C137  1uF  [CC0805_OV]
D4  PMEG4002EB  [SOD523]
D112  PESD5V0C1BLS-QYL  [sod882bd]
D113  PESD5V0C1BLS-QYL  [sod882bd]
D114  PESD5V0C1BLS-QYL  [sod882bd]
F1  0ZCK0050FF2E  [fuse_2p2x1p5_49h]
J1  USB_TYPE_C  [con16_usb_type-c_ra_sm]
J2  CON 1X6 SKT  [con1x6_2p0mm_sm]
L8  120Ohms@100MHz  [IND_0402]
R1  5.1K  [RC0402_25]
R2  2.2K  [RC0402_25]
R3  2.2K  [RC0402_25]
R4  100k  [RC0402_25]
R6  300  [RC0603_OV]
R48  30K  [RC0402_25]
R49  10K  [RC0402_25]
R50  10K  [RC0402_25]
R51  10K  [RC0402_25]
R54  5.1K  [RC0402_25]
R61  120  [RC0402_25]
R62  120  [RC0402_25]
TP3  TPAD_030  [TPAD_030]
TP14  TPAD_030  [TPAD_030]
TP15  TP_OB2x1.5MM  [testpoint_ob2x1p5mm_sm]
TP16  TP_OB2x1.5MM  [testpoint_ob2x1p5mm_sm]
U2  TLV75733PDRVR  [wson6_0p65_2p1x2p1]
U3  MIMXRT1064DVJ6B  [bga196_0p8_12x12mm_a]  (sections A,B,C,D,E,F)
U13  NX5P3363UKZ  [bga16_0p5_2p23x2p23]
U19  NCP151AAMX330180TCG  [dfn1010-4_epad0p4]

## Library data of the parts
C38-C41 C43-C46 C49 C51 C52 C55 C58-C63 C85 C91 C95 C98 C99 C105 C106 C110 C111 C116-C119 C134 = CAP_NP: CAP CER 0.1UF 6.3V 10% X5R 0201; AGILE_PN: 150-75429; CAD_APPROVED: Yes; FPLIST: CC0201,CC0201_HD,CC0201_3PIN,0201_CC,0201_CC_012SM_NSP,CC_0201_L; HEIGHT: 0.33; MFG_NAME01: MURATA; MFG_PN01: GRM033R60J104KE19D; Package Size: 0201; Package Type: SMD; ROHS: Yes; Rated Voltage: 6.3V; Temp Range: -55C to +85C; Tolerance: 10%
C129 = CAP_NP: CAP CER 4700pF 250V 10% X7R AEC-Q200 0805; AGILE_PN: 150-80512; CAD_APPROVED: Yes; FPLIST: CC0805_OV,CC0805,0805_CC; HEIGHT: 1; MFG_NAME01: MURATA; MFG_PN01: GCJ21AR72E472KXJ1D; ROHS: Yes; Rated Voltage: 250V; Temp Range: -55C to +125C; Tolerance: 10%
C3 C130 C133 C137 = CAP_NP: CAP CER 1uF 25V 10% X7R AEC-Q200 0805; AGILE_PN: 150-79250; CAD_APPROVED: Yes; FPLIST: CC0805_OV,CC0805,0805_CC; HEIGHT: 1.4; MFG_NAME01: MURATA; MFG_PN01: GCM21BR71E105KA56L; Package Size: 0805; ROHS: Yes; Rated Voltage: 25V; Temp Range: -55C to +125C; Tolerance: 10%
D6 D10 D106 = DIODE_SCHTKY: DIODE SCH RECT 2A 20V AEC-Q101 SMD; 3D_Mechanical_Footprint_File: http://fcl.am.freescale.net/ALLEGRO/step/dfn1608d-2.STEP; AGILE_PN: 480-79688; CAD_APPROVED: Yes; HEIGHT: 0.4; MFG_NAME01: NEXPERIA; MFG_PN01: PMEG2020EPK,315; Rated Voltage: 60V
D107 = DIODE_NUP2105L: DIODE DUAL LINE CAN BUS PROTECTOR 27V 350W SOT-23; AGILE_PN: 480-77157; CAD_APPROVED: Yes; HEIGHT: 1.11; MFG_NAME01: ON SEMICONDUCTOR; MFG_PN01: NUP2105LT1G
F1 F2 = FUSE_RESETTABLE: FUSE PTC 500mA 6V AEC-Q200 0805; 3D_Mechanical_Footprint_File: http://fcl.am.freescale.net/ALLEGRO/step/fuse_2p2x1p5_49h.step; AGILE_PN: 510-10056; CAD_APPROVED: yes; HEIGHT: 1.25mm; MFG_NAME01: BEL FUSE; Package Type: Surface Mount; ROHS: NULL; Rated Current: 100 A; Temp Range: -40 °C to +85 °C
FL1-FL5 FL7 FL8 = EMIFILTER_C: CAP FILTER EMI 0.1uF 16V 20% -- 0603; 3D_Mechanical_Footprint_File: http://fcl.am.freescale.net/ALLEGRO/step/cc0603_nfm18pc.STEP; AGILE_PN: 150-10138; CAD_APPROVED: Yes; HEIGHT: 0.7; MFG_NAME01: MURATA; Package Size: 0.063" L x 0.032" W; Package Type: Surface Mount; ROHS: NULL; Temp Range: -55 °C to +125 °C; Tolerance: 20%
J3 = CON_HDR_1X10_2SH: CON 1X10 PLUG SHRD SMT RA 1MM SP 116H SN; 3D_Mechanical_Footprint_File: http://fcl.am.freescale.net/ALLEGRO/step/con_10m_1mm_sm_ra.STEP; AGILE_PN: 211-10200; CAD_APPROVED: Yes; Contact Voltage: 50V; HEIGHT: 2.95mm; MFG_NAME01: JST MFG. CO; MFG_PN01: SM10B-SRSS-TB(LF)(SN); Package Size: 12 x 4.25 mm; Package Type: Surface Mount, Right Angle; ROHS: NULL; Temp Range: -25°C to 85°C
J4 = BM10B-GHS_CON_1X10: CON 1X10 CRIMP SMT 1.25MM SP 161H SN; 3D_Mechanical_Footprint_File: http://fcl.am.freescale.net/ALLEGRO/step/con_1x10_1p25_15p75x4p25_sm.STEP; AGILE_PN: 211-80511; CAD_APPROVED: Yes; HEIGHT: 4.1; MFG_NAME01: JST MFG. CO; MFG_PN01: BM10B-GHS-TBT(LF)(SN)(N); ROHS: Yes; Temp Range: -25° C to + 85° C
J5 J10 J11 = CONN_1x4_SHLD: CON 1X4 CRIMP SMT 1.25MM SP 159H SN; 3D_Mechanical_Footprint_File: http://fcl.am.freescale.net/ALLEGRO/step/con_1x4_1p25_8p25x4p25_sm.STEP; AGILE_PN: 211-80221; CAD_APPROVED: Yes; HEIGHT: 4.1; MFG_NAME01: JST MFG. CO; MFG_PN01: BM04B-GHS-TBT(LF)(SN)(N); Package Type: SMT; ROHS: Yes; Temp Range: -25C to +85C
J7-J9 = CONN_1x6_SHLD: CON 1X6 CRIMP SMT 1.25MM SP 159H SN; 3D_Mechanical_Footprint_File: http://fcl.am.freescale.net/ALLEGRO/step/con_1x6_1p25_10p75x4p25_sm.STEP; AGILE_PN: 211-80220; CAD_APPROVED: Yes; HEIGHT: 4.1; MFG_NAME01: JST MFG. CO; MFG_PN01: BM06B-GHS-TBT(LF)(SN)(N); Package Type: SMT; ROHS: Yes; Temp Range: -25C to +85C
J12 = CONN_HDR_8X1: CON 1x8 PLUG RA SHRD SMT 1MM SP 116H SN; 3D_Mechanical_Footprint_File: http://fcl.am.freescale.net/ALLEGRO/step/plug1x8_1mm_shrd_sm.STEP; AGILE_PN: 211-79281; CAD_APPROVED: Yes; Contact Voltage: 50V; HEIGHT: 2.95mm; MFG_NAME01: JST MFG. CO; MFG_PN01: SM08B-SRSS-TB(LF)(SN); Package Size: 10 x 4.25 mm; Package Type: SMD/SMT; ROHS: NULL; SILK: PWM_B; Temp Range: -25°C to 85°C
J13 = CONN_HDR_8X1: CON 1x8 PLUG RA SHRD SMT 1MM SP 116H SN; 3D_Mechanical_Footprint_File: http://fcl.am.freescale.net/ALLEGRO/step/plug1x8_1mm_shrd_sm.STEP; AGILE_PN: 211-79281; CAD_APPROVED: Yes; Contact Voltage: 50V; HEIGHT: 2.95mm; MFG_NAME01: JST MFG. CO; MFG_PN01: SM08B-SRSS-TB(LF)(SN); Package Size: 10 x 4.25 mm; Package Type: SMD/SMT; ROHS: NULL; SILK: PWM_A; Temp Range: -25°C to 85°C
Q1 = MOSFET_N: TRAN NMOS SW 5.7A 30V SOT23; 3D_Mechanical_Footprint_File: http://fcl.am.freescale.net/ALLEGRO/step/SOT-23W.step; AGILE_PN: 480-78353; CAD_APPROVED: Yes; HEIGHT: 1.25; MFG_NAME01: ALPHA AND OMEGA SEMICONDUCTOR; ROHS: Yes
R9 R10 = RES: RES MF 60.4 OHM 1/4W 1% AEC-Q200 0402; 3D_Mechanical_Footprint_File: http://fcl.am.freescale.net/ALLEGRO/step/rc0402_25.STEP; AGILE_PN: 470-83407; CAD_APPROVED: Yes; FPLIST: RC0402_25,RC0402_HD,0402_CC; HEIGHT: 0.4; MFG_NAME01: Panasonic; MFG_PN01: ERJ-PA2F60R4X; Package Type: PCB Mount; ROHS: Yes; Temp Range: -55°C ~ 155°C; Tolerance: 1%
R2 R3 R13 R14 R27 R28 = RES: RES MF 2.2K 1/16W 5% 0402; AGILE_PN: 470-76602; CAD_APPROVED: Yes; FPLIST: RC0402_25,RC0402_HD,0402_CC; HEIGHT: 0.4; MFG_NAME01: YAGEO AMERICA; MFG_PN01: RC0402JR-072K2L; ROHS: Yes; Tolerance: 5%
R31 = RES: RES MF 1K 1/16W 1% AEC-Q200 0402; 3D_Mechanical_Footprint_File: http://fcl.am.freescale.net/ALLEGRO/step/rc0402_25.STEP; AGILE_PN: 470-83212; CAD_APPROVED: Yes; FPLIST: rc0402_25,rc0402_hd,0402_cc; HEIGHT: 0.4; MFG_NAME01: STACKPOLE ELECTRONICS; MFG_PN01: RMCF0402FT1K00; Package Size: 0402 (1005 Metric); Package Type: SMD/SMT; ROHS: Yes; Temp Range: -55°C to +155°C; Tolerance: ±1%
R33 R60 = RES: RES MF 10K 1/5W 1% AEC-Q200 0402; AGILE_PN: 470-80881; CAD_APPROVED: Yes; FPLIST: RC0402_25,RC0402_HD,0402_CC; HEIGHT: 0.4; MFG_NAME01: VISHAY INTERTECHNOLOGY; MFG_PN01: CRCW040210K0FKEDHP; ROHS: Yes; Temp Range: -55&#8451; to 155&#8451;; Tolerance: 1%
R41 = RES: RES MF 680 OHM 1/16W 5% 0402; AGILE_PN: 470-77301; CAD_APPROVED: Yes; FPLIST: RC0402_25,RC0402_HD,0402_CC; HEIGHT: 0.4; MFG_NAME01: PANASONIC; MFG_PN01: ERJ-2GEJ681X; ROHS: Yes; Temp Range: -55C to 155C; Tolerance: 5%
R42 R52 R64 = RES: RES MF 220 OHM 1/10W 5% AEC-Q200 0402; AGILE_PN: 470-82062; CAD_APPROVED: Yes; FPLIST: RC0402_25,RC0402_HD,0402_CC; HEIGHT: 0.45; MFG_NAME01: KOA SPEER; MFG_PN01: RK73B1ETTP221J; ROHS: Yes; Temp Range: -55C to +155C; Tolerance: 5%
R43 R44 R61 R62 = RES: RES MF 120 OHM 1/16W 1% 0402; 3D_Mechanical_Footprint_File: http://fcl.am.freescale.net/ALLEGRO/step/rc0402_25.STEP; AGILE_PN: 470-30149; CAD_APPROVED: Yes; FPLIST: RC0402_25,RC0402_HD,0402_CC,rc0402_ghwe; HEIGHT: 0.4; MFG_NAME01: VISHAY INTERTECHNOLOGY; MFG_PN01: CRCW0402120RFKED; ROHS: Yes; Tolerance: 1%
R15 R16 R18 R19 R22 R25 R47 R49-R51 R53 R55 R59 = RES: RES MF 10K 1/5W 1% AEC-Q200 0402; AGILE_PN: 470-80881; CAD_APPROVED: Yes; FPLIST: RC0402_25,RC0402_HD,0402_CC; HEIGHT: 0.4; MFG_NAME01: VISHAY INTERTECHNOLOGY; MFG_PN01: CRCW040210K0FKEDHP; ROHS: Yes; ROOM: OPENSDA MCU; TOL: 1%; Temp Range: -55&#8451; to 155&#8451;; Temp_Range: -55&#8451; to 155&#8451;; Tolerance: 1%
RN1 RN3-RN7 = Resistor_Array: RNET ISO 4 220 OHM 1/16W 5% AEC-Q200 1206; 3D_Mechanical_Footprint_File: http://fcl.am.freescale.net/ALLEGRO/step/rnet_38v_0603.step; AGILE_PN: 470-82464; CAD_APPROVED: Yes; HEIGHT: 0.6; MFG_NAME01: PANASONIC; MFG_PN01: EXB-38V221JV; ROHS: Yes; Temp Range: -55C to +125C; Tolerance: 5%
U16 = TJA1462ATK_HVSON8: IC XCVR CAN 4.5-5.5V AEC-Q100 HVSON8; 3D_Mechanical_Footprint_File: http://fcl.am.freescale.net/ALLEGRO/step/son8_0p65_3p15x3p15.STEP; AGILE_PN: 312-83227; CAD_APPROVED: Yes; HEIGHT: 1; MFG_NAME01: NXP SEMICONDUCTORS; Package Size: 8-VDFN Exposed Pad; ROHS: Yes; Supply Voltage: 4.5V ~ 5.5V; Temp Range: -40  °C to +150 °C
C37 C42 C47 C50 = CAP_NP: CAP CER 1uF 10V 10% X7S 0402; AGILE_PN: 150-80357; CAD_APPROVED: Yes; FPLIST: CC0402_25,CC0402_HD,0402_CC,capc0402_l; HEIGHT: 0.6; MFG_NAME01: MURATA; MFG_PN01: GRM155C71A105KE11D; Package Size: 0402; ROHS: Yes; Rated Voltage: 10V; Temp Range: -55C to +125C; Tolerance: 10%; VOLTAGE: 25V
C48 C80 C83 C135 = CAP_NP: CAP CER 10uF 10V 20% X5R 0402; AGILE_PN: 150-80620; CAD_APPROVED: Yes; FPLIST: cc0402_tol0p2,cc0402_tol0p2_ov,0402_cc_nsp; HEIGHT: 0.7MM; MFG_NAME01: MURATA; MFG_PN01: GRM155R61A106ME11; Package Size: 0402; Package Type: SMD; ROHS: NULL; Rated Voltage: 10V; Temp Range: -55C to +85C; Tolerance: 20%
C53 = CAP_NP: CAP CER 4700pF 50V 10% X7R AEC-Q200 0402; AGILE_PN: 150-79034; CAD_APPROVED: Yes; FPLIST: CC0402_25,CC0402_HD,0402_CC,capc0402_l; HEIGHT: 0.55; MFG_NAME01: MURATA; MFG_PN01: GCM155R71H472KA37D; Package Size: 0402; ROHS: Yes; Rated Voltage: 50V; Temp Range: -55C to +125C; Tolerance: 10%; VOLTAGE: 50V
D7 = ESD_DIODE_2LINE: DIODE 2 CH ESD PROTECTOR 30KV 24V AEC-Q101 SOT23; AGILE_PN: 480-80185; CAD_APPROVED: Yes; HEIGHT: 1.1; MFG_NAME01: NEXPERIA; Temp Range: -55°C to 150°C
D8 = LED: LED AMB SGL 2V 20mA 0603; 3D_Mechanical_Footprint_File: http://fcl.am.freescale.net/ALLEGRO/step/LED_0603.STEP; AGILE_PN: 370-76859; CAD_APPROVED: Yes; HEIGHT: 0.8MM; MFG_NAME01: WURTH ELEKTRONIK EISOS GMBH & CO. KG (ELECTRONIC & ELECTROMEHANICAL COMP); MFG_PN01: 150060AS75000; Temp Range: -40 C TO -85 C
D9 = LED: LED BRIGHT GRN SGL 30mA 0603; AGILE_PN: 370-76670; CAD_APPROVED: Yes; HEIGHT: 0.8MM; MFG_NAME01: WURTH ELEKTRONIK EISOS GMBH & CO. KG (ELECTRONIC & ELECTROMEHANICAL COMP); MFG_PN01: 150060VS75000
FL6 = FILTER_4P: FILTER COMMON MODE 200uH@100KHZ 70mA +30/-10% AEC-Q200 SMT; 3D_Mechanical_Footprint_File: http://fcl.am.freescale.net/ALLEGRO/step/ind_act1210_sm.STEP; AGILE_PN: 180-78762; CAD_APPROVED: Yes; HEIGHT: 2.5; MFG_NAME01: TDK; MFG_PN01: ACT1210L-201-2P-TL00; Package Size: 1210; ROHS: Yes; Temp Range: -40C to +125C; VOLTAGE: 80V
L3-L5 = BEAD: IND FER BEAD 600 OHM@100MHZ 0.5A 25% AEC-Q200 0603; 3D_Mechanical_Footprint_File: http://fcl.am.freescale.net/ALLEGRO/step/ind_0603.STEP; AGILE_PN: 180-81156; CAD_APPROVED: Yes; FPLIST: IND_0603,0603_CC; HEIGHT: 0.95; MFG_NAME01: MURATA; MFG_PN01: BLM18AG601BH1D; Package Size: 0603 (1608 Metric); ROHS: Yes; Temp Range: -55°C to +150°C
P1 = CONN_2X1_SH: CON 1X2 CRIMP SMT 1.25MM SP 159H SN; 3D_Mechanical_Footprint_File: http://fcl.am.freescale.net/ALLEGRO/step/con_1x2_1p25_5p75x4p25_sm.STEP; AGILE_PN: 211-80321; CAD_APPROVED: Yes; HEIGHT: 4.1; MFG_NAME01: JST MFG. CO; MFG_PN01: BM02B-GHS-TBT(LF)(SN)(N); ROHS: Yes; Temp Range: -25C to +85C
R20 R21 = RES: RES MF 1.0K 0.4W 1% AEC-Q200 0805; AGILE_PN: 470-81930; CAD_APPROVED: Yes; FPLIST: RC0805_OV,RC0805,0805_CC; HEIGHT: 0.65; MFG_NAME01: ROHM; MFG_PN01: ESR10EZPF1001; ROHS: Yes; Temp Range: -55C to +155C; Tolerance: 1%
R23 R24 = RES: RES MF 680 OHM 1/16W 5% 0402; AGILE_PN: 470-77301; CAD_APPROVED: Yes; FPLIST: RC0402_25,RC0402_HD,0402_CC; HEIGHT: 0.4; MFG_NAME01: PANASONIC; MFG_PN01: ERJ-2GEJ681X; ROHS: Yes; Temp Range: -55C to 155C; Tolerance: 5%; VOLTAGE: 50V
R4 R26 = RES: RES MF 100k Ohm 1/16W 1% AEC-Q200 0402; AGILE_PN: 470-80502; CAD_APPROVED: Yes; FPLIST: RC0402_25,RC0402_HD,0402_CC; HEIGHT: 0.4; MFG_NAME01: KOA SPEER; MFG_PN01: RK73H1ETTP1003F; ROHS: NULL; Temp Range: -55° C to +155° C; Tolerance: 1%
TP11 = TESTLOOP: TEST POINT PAD 30MIL DIA SMT, NO PART TO ORDER; 3D_Mechanical_Footprint_File: http://fcl.am.freescale.net/ALLEGRO/step/tpad_030.STEP; AGILE_PN: 211-76642; CAD_APPROVED: Yes; HEIGHT: 0.1; MFG_NAME01: NOTACOMPONENT; MFG_PN01: NOTACOMPONENT; NOTE: TPAD; ROHS: Yes; ROOM: LIN PHY
U5 = TJA1103A_HVQFN36: IC ETHERNET PHY 3.3/2.5/1.1V AEC-Q100 HVQFN36; AGILE_PN: 312-82945; CAD_APPROVED: Yes; HEIGHT: 1.0; MFG_NAME01: NXP SEMICONDUCTORS; Package Size: 6.0 x 6.0 x 0.85MM; ROHS: NULL; Supply Voltage: 3.3/2.5/1.1V; Temp Range: -40C to +125C; VOLTAGE: 3.3/2.5/1.1V
C26 C66 = CAP_NP: CAP CER 8pF 50V 1% C0G AEC-Q200 0402; 3D_Mechanical_Footprint_File: http://fcl.am.freescale.net/ALLEGRO/step/cc0402_25.STEP; AGILE_PN: 150-10093; CAD_APPROVED: Yes; FPLIST: CC0402_25,CC0402_HD,0402_CC,capc0402_l; HEIGHT: 0.55; MFG_NAME01: MURATA; MFG_PN01: GCM1555C1H8R0FA16D; Package Size: 0402; Package Type: SMD/SMT; ROHS: NULL; Rated Voltage: 50V; Temp Range: -55C to +125C; Tolerance: 1%
C28 C84 = CAP_NP: CAP CER 12PF 50V 5% C0G 0402; 3D_Mechanical_Footprint_File: http://fcl.am.freescale.net/ALLEGRO/step/cc0402_25.STEP; AGILE_PN: 150-75680; CAD_APPROVED: Yes; FPLIST: CC0402_25,CC0402_HD,0402_CC,capc0402_l; HEIGHT: 0.55mm; MFG_NAME01: NIC COMPONENTS CORP; MFG_PN01: NMC0402NPO120J50TRPF; Package Size: 0402 (1005 Metric); Package Type: SMD/SMT; ROHS: NULL; Rated Voltage: 50V; Temp Range: -55C to +125C; Tolerance: 5%
C65 = CAP_NP: CAP CER 10UF 10V 10% X5R 0603; AGILE_PN: 150-78675; CAD_APPROVED: Yes; FPLIST: CC0603_OV,CC0603,0603_CC_NSP; HEIGHT: 1.016; MFG_NAME01: MURATA; MFG_PN01: GRM188R61A106KE69D; ROHS: Yes; Rated Voltage: 10V; Temp Range: -55C to +85C; Tolerance: 10%
C8 C67-C74 C77 C79 C89 C92 C93 C138 = CAP_NP: CAP CER 0.22UF 10V 10% X5R 0201; AGILE_PN: 150-80206; CAD_APPROVED: Yes; FPLIST: CC0201,CC0201_HD,0201_CC; HEIGHT: 0.33; MFG_NAME01: MURATA; MFG_PN01: GRM033R61A224KE90; ROHS: Yes; Rated Voltage: 10V; Temp Range: -55C to +85C; Tolerance: 10%
C81 C96 C97 C100 C124 C125 C128 = CAP_NP: CAP CER 4.7uF 10V 20% X6S AEC-Q200 0402; 3D_Mechanical_Footprint_File: http://fcl.am.freescale.net/ALLEGRO/step/cc0402_tol0p2.STEP; AGILE_PN: 150-10049; CAD_APPROVED: Yes; FPLIST: cc0402_tol0p2,cc0402_tol0p2_ov,cc0402_25_tol0p2,0402_cc_nsp; HEIGHT: 0.7mm; MFG_NAME01: MURATA; MFG_PN01: GRT155C81A475ME13J; Package Size: 0402 (1005 metric); Package Type: SMD/SMT; ROHS: NULL; Rated Voltage: 10 VDC; Temp Range: -55°C to 105°C; Tolerance: 20%
C131 = CAP_NP: CAP CER 0.1uF 16V 10% X5R 0201; 3D_Mechanical_Footprint_File: http://fcl.am.freescale.net/ALLEGRO/step/cc0201.STEP; AGILE_PN: 150-80059; CAD_APPROVED: Yes; FPLIST: CC0201,CC0201_HD,0201_CC; HEIGHT: 0.33; MFG_NAME01: MURATA; MFG_PN01: GRM033R61C104KE14D; Package Size: 0201; ROHS: Yes; Rated Voltage: 16V; Temp Range: -55C to +85C; Tolerance: 10%
C136 = CAP_NP: CAP CER 22UF 6.3V 20% X5R 0603; AGILE_PN: 150-78467; CAD_APPROVED: Yes; FPLIST: CC0603_OV,CC0603,0603_CC; HEIGHT: 1; MFG_NAME01: SAMSUNG; MFG_PN01: CL10A226MQ8NRNE; Package Size: 0603; ROHS: NULL; Rated Voltage: 6.3V; Temp Range: -55C to +85C; Tolerance: 20%; VOLTAGE: 6.3V; voltage rating: 6.3V
CN1 = CONN_MICRO_SD_CARD: CON 8 MICRO SD CARD PUSH-PUSH SMT 1.1MM SP 55H AU; 3D_Mechanical_Footprint_File: http://fcl.am.freescale.net/ALLEGRO/step/con8_microsdcard_1p1mm_sm.step; AGILE_PN: 211-80524; CAD_APPROVED: Yes; HEIGHT: 1.4; MFG_NAME01: MOLEX; MFG_PN01: 5033981892; Package Type: SMT; ROHS: Yes; Temp Range: -25° C to + 85°C
D2 = DUALDIODE_CC_SOT23: DIODE SCH 200mA 30V AEC-Q101 SOT23; 3D_Mechanical_Footprint_File: http://fcl.am.freescale.net/ALLEGRO/step/sot23_a.STEP; AGILE_PN: 480-80822; CAD_APPROVED: YES; HEIGHT: 1.1; MFG_NAME01: ON Semiconductor; Temp Range: -55°C ~ 125°C
L7 L8 = INDUCTOR: IND FER 120OHM@100MHZ 2A 25% 0402; AGILE_PN: 180-79553; CAD_APPROVED: Yes; FPLIST: IND_0402,0402_CC; HEIGHT: 0.55; MFG_NAME01: MURATA; MFG_PN01: BLM15PX121SN1D; Package Size: 0402 (1005 Metric); ROHS: Yes; Temp Range: -55C to +125C
L9 = INDUCTOR: IND PWR 4.7UH@1MHZ 1.1A 20% 1008; AGILE_PN: 180-77593; CAD_APPROVED: Yes; HEIGHT: 1; MFG_NAME01: MURATA; MFG_PN01: LQM2HPN4R7MG0L; ROHS: Yes
R8 = RES: RES MF 2.2M 1/10W 1% AEC-Q200 0402; AGILE_PN: 470-31210; CAD_APPROVED: Yes; FPLIST: RC0402_25,RC0402_HD,0402_CC; HEIGHT: 0.40; MFG_NAME01: KOA SPEER; MFG_PN01: RK73H1ETTP2204F; ROHS: Yes; Temp Range: -55C to +155C; Tolerance: 1%
R48 R63 = RES: RES MF 30K 1/10W 5% AEC-Q200 0402; 3D_Mechanical_Footprint_File: http://fcl.am.freescale.net/ALLEGRO/step/rc0402_25.STEP; AGILE_PN: 470-83326; CAD_APPROVED: Yes; FPLIST: RC0402_25,RC0402_HD,0402_CC; HEIGHT: 0.40; MFG_NAME01: PANASONIC; MFG_PN01: ERJ-2GEJ303X; Package Size: 0402 (1005 Metric); Package Type: SMD/SMT; ROHS: Yes; Temp Range: -55C to +155C; Tolerance: 5%
SW2 = SW2P: SW SPST NO TACT 0.02A 15V SMT; 3D_Mechanical_Footprint_File: http://fcl.am.freescale.net/ALLEGRO/step/sw2_tact_2p1x1p65_sm.STEP; AGILE_PN: 510-10049; CAD_APPROVED: Yes; HEIGHT: 0.55mm; MFG_NAME01: C&K COMPONENTS; Package Size: 2.10mm x 1.65mm; ROHS: NULL; Temp Range: -40°C to 85°C
TP9 = T_POINT_R: TEST POINT PAD .035 SMT, no part to order; AGILE_PN: 510-75618; CAD_APPROVED: Yes; HEIGHT: 0.1; ROHS: Yes
U17 = MIC803_8P: IC MPU VOLTAGE SUPERVISOR 1.2-5.5V SC70-3; 3D_Mechanical_Footprint_File: http://fcl.am.freescale.net/ALLEGRO/step/sc70_3.STEP; AGILE_PN: 312-82718; CAD_APPROVED: Yes; HEIGHT: 1.1; MFG_NAME01: MICROCHIP TECHNOLOGY INC; Package Size: SC-70, SOT-323; ROHS: Yes; Supply Voltage: 1.0-5.5V; Temp Range: -40C to +125C; VOLTAGE: 1.0-5.5V
Y1 = XTAL_13: XTAL 24MHz 8pF 3225 SMD; 3D_Mechanical_Footprint_File: http://fcl.am.freescale.net/ALLEGRO/step/xtal4_cx3225ca_sm.STEP; AGILE_PN: 230-78517; CAD_APPROVED: YES; Frequency Tolerance: 10 PPM; HEIGHT: 0.6; MFG_NAME01: Kyocera Electronic Components; MFG_PN01: CX3225SB24000D0FLJCC; Package Size: 3.2 mm x 2.5 mm; ROHS: YES; Temp Range: -30 C to +85 C
Y2 = XTAL: XTAL 32.768kHz 12.5pF 10PPM SMD; 3D_Mechanical_Footprint_File: http://fcl.am.freescale.net/ALLEGRO/step/xtal2_2p1x1p3_sm.STEP; AGILE_PN: 230-10042; CAD_APPROVED: YES; Frequency Tolerance: 10ppm; HEIGHT: 0.6MM; MFG_NAME01: ECS INC. INTERNATIONAL; MFG_PN01: ECS-.327-12.5-12-C-TR; Package Size: 2.00mm x 1.20mm; ROHS: NULL; Temp Range: -40  °C to +85 °C
C54 = CAP_NP: CAP CER 0.01uF 6.3V 10% X7R AEC-Q200 0201; 3D_Mechanical_Footprint_File: http://fcl.am.freescale.net/ALLEGRO/step/cc0201.STEP; AGILE_PN: 150-81902; CAD_APPROVED: Yes; FPLIST: CC0201,CC0201_HD,0201_CC; HEIGHT: 0.33; MFG_NAME01: TDK; MFG_PN01: CGA1A2X7R0J103K030BA; Package Size: 0201; Package Type: SMD/SMT; ROHS: Yes; Rated Voltage: 6.3 VDC; Temp Range: -55C to +125C; Tolerance: 10%
C56 C57 = CAP_NP: CAP CER 2.2uF 10V 10% X7S 0402; AGILE_PN: 150-79706; CAD_APPROVED: Yes; FPLIST: cc0402_tol0p15,cc0402_tol0p15_ov,0402_cc_tol,0402_cc_nsp; HEIGHT: 0.65; MFG_NAME01: TDK; MFG_PN01: C1005X7S1A225K050BC; Package Size: 0402; ROHS: Yes; Rated Voltage: 10V; Temp Range: -55C to +125C; Tolerance: 10%
C64 = CAP_NP: CAP CER 2200PF 16V 10% X7R 0201; AGILE_PN: 150-78660; CAD_APPROVED: Yes; FPLIST: CC0201,CC0201_HD,0201_CC; HEIGHT: 0.33; MFG_NAME01: MURATA; MFG_PN01: GRM033R71C222KA88D; ROHS: Yes; Rated Voltage: 16V; Temp Range: -55C to +125C; Tolerance: 20%
TP3 TP14 TP17 TP18 = TestLoop: TEST POINT PAD 30MIL DIA SMT, NO PART TO ORDER; 3D_Mechanical_Footprint_File: http://fcl.am.freescale.net/ALLEGRO/step/tpad_030.STEP; AGILE_PN: 211-76642; CAD_APPROVED: Yes; HEIGHT: 0.1; MFG_NAME01: NOTACOMPONENT; MFG_PN01: NOTACOMPONENT; ROHS: Yes
U6 = BMM350_9P: IC GEOMAGNETIC SENSOR 3-AXIS I2C/I3C 1.72-1.98/1.72-3.6V WLCSP9; 3D_Mechanical_Footprint_File: http://fcl.am.freescale.net/ALLEGRO/step/wlcsp9_0p4_1p28sq.STEP; AGILE_PN: 312-10101; CAD_APPROVED: Yes; HEIGHT: 0.54mm; MFG_NAME01: Bosch Sensortec GmbH; Package Size: 1.28 x 1.28 x 0.5 mm; ROHS: NULL; Supply Voltage: 1.72V ~ 1.98V; Temp Range: -40°C to 85°C
U7 = ICM-45686_LGA14: IC MEMS 6-AXIS MOTION SENSOR 1.71-3.6V LGA14; 3D_Mechanical_Footprint_File: http://fcl.am.freescale.net/ALLEGRO/step/lga14_0p5_3x2p5.STEP; AGILE_PN: 315-10403; CAD_APPROVED: Yes; HEIGHT: 0.86mm; MFG_NAME01: TDK; Package Size: 14-VFLGA; ROHS: NULL; Temp Range: -40°C to +85°C
U8 = BMP390_10P: IC PRESSURE SENSOR 300-1250hPA I2C SPI 1.65-3.6V LGA10; 3D_Mechanical_Footprint_File: http://fcl.am.freescale.net/ALLEGRO/step/lga10_0p5_2x2.STEP; AGILE_PN: 312-10100; CAD_APPROVED: Yes; HEIGHT: 0.8mm; MFG_NAME01: Bosch Sensortec GmbH; Package Size: 2 x 2 x 0.75 mm; ROHS: NULL; Supply Voltage: 1.65V ~ 3.6V; Temp Range: -40°C to 85°C; VOLTAGE: 1.65V ~ 3.6V
U9 = BMI088_16P: IC ACCELERATION SENSOR 6-AXIS 2/4/8/16G 2.4-3.6V LGA16; 3D_Mechanical_Footprint_File: http://fcl.am.freescale.net/ALLEGRO/step/lga16_0p5_3x4p5mm.STEP; AGILE_PN: 312-82852; CAD_APPROVED: Yes; HEIGHT: 1; MFG_NAME01: Bosch Sensortec; Package Size: 16-VFLGA Module; ROHS: Yes; Temp Range: -40°C ~ 85°C; VOLTAGE: 2.4-3.6V
J6 = BM08B-GHS_CON_1X8: CON 1X8 CRIMP SMT 1.25MM SP 159H SN; 3D_Mechanical_Footprint_File: http://fcl.am.freescale.net/ALLEGRO/step/con_1x8_1p25_13p25x4p25_sm.STEP; AGILE_PN: 211-80518; CAD_APPROVED: Yes; HEIGHT: 4.1; MFG_NAME01: JST MFG. CO; MFG_PN01: BM08B-GHS-TBT(LF)(SN)(N); ROHS: Yes; Temp Range: -25°C ~ 85°C
R56-R58 = RES: RES MF 620 OHM 1/10W 1% AEC-Q200 0402; AGILE_PN: 470-30816; CAD_APPROVED: Yes; FPLIST: RC0402_25,RC0402_HD,0402_CC; HEIGHT: 0.40; MFG_NAME01: KOA SPEER; MFG_PN01: RK73H1ETTP6200F; ROHS: Yes; Temp Range: -55°C to +155°C; Tolerance: 1%
U10 = LED_RGB_6P: LED RGB SGL 30mA 2/3.2/3.2V SMT; 3D_Mechanical_Footprint_File: http://fcl.am.freescale.net/ALLEGRO/step/led6_0p85_3p25x2p85_sm.step; AGILE_PN: 370-76822; CAD_APPROVED: YES; HEIGHT: 1.85; MFG_NAME01: WURTH ELEKTRONIK EISOS GMBH & CO. KG (ELECTRONIC & ELECTROMEHANICAL COMP)
C6 C15 = CAP_NP: CAP CER 47UF 10V 10% X7R 1210; AGILE_PN: 150-30186; CAD_APPROVED: Yes; FPLIST: CC1210,1210_CC; HEIGHT: 2.7; MFG_NAME01: MURATA; MFG_PN01: GRM32ER71A476KE15L; ROHS: Yes; Rated Voltage: 10V; Temp Range: -55C to +125C; Tolerance: 10%
C13 C126 C127 = CAP_NP: CAP CER 4.7uF 10V 20% X6S AEC-Q200 0402; 3D_Mechanical_Footprint_File: http://fcl.am.freescale.net/ALLEGRO/step/cc0402_tol0p2.STEP; AGILE_PN: 150-10049; CAD_APPROVED: Yes; FPLIST: cc0402_tol0p2,cc0402_tol0p2_ov,cc0402_25_tol0p2,0402_cc_nsp; HEIGHT: 0.7mm; MFG_NAME01: MURATA; MFG_PN01: GRT155C81A475ME13J; Package Size: 0402 (1005 metric); Package Type: SMD/SMT; ROHS: NULL; Rated Voltage: 10 VDC; Temp Range: -55°C to 105°C; Tolerance: 20%; VOLTAGE: 6.3V; voltage rating: 6.3V
C86 = CAP_NP: CAP CER 1000pF 50V 10% X7R AEC-Q200 0402; AGILE_PN: 150-79040; CAD_APPROVED: Yes; FPLIST: CC0402_25,CC0402_HD,0402_CC,capc0402_l; HEIGHT: 0.55MM; MFG_NAME01: MURATA; MFG_PN01: GCM155R71H102KA37D; Package Size: 0402; Package Type: Paper Tape; ROHS: NULL; Rated Voltage: 50V; Temp Range: -55C to +125C; Tolerance: 10%
C90 C114 = CAP_NP: CAP CER 1uF 10V 10% X7S 0402; AGILE_PN: 150-80357; CAD_APPROVED: Yes; FPLIST: CC0402_25,CC0402_HD,0402_CC,capc0402_l; HEIGHT: 0.6; MFG_NAME01: MURATA; MFG_PN01: GRM155C71A105KE11D; Package Size: 0402; ROHS: Yes; Rated Voltage: 10V; Temp Range: -55C to +125C; Tolerance: 10%
D4 = DIODE_SCHTKY: DIODE SCH PWR RECT 0.2A 40V SOD523; 3D_Mechanical_Footprint_File: http://fcl.am.freescale.net/ALLEGRO/step/SOD523.STEP; AGILE_PN: 480-10112; CAD_APPROVED: Yes; HEIGHT: 0.65; MFG_NAME01: NEXPERIA; MFG_PN01: PMEG4002EB,115; Package Size: SC-79, SOD-523; Rated Voltage: 600 mV @ 200 mA; Temp Range: -65C to +150C
D112-D114 = DIODE_BIDIR: DIODE ESD PROTECTION BIDIR 5V 15kV AEC-Q101 SOD882BD; 3D_Mechanical_Footprint_File: http://fcl.am.freescale.net/ALLEGRO/step/sod882bd.STEP; AGILE_PN: 480-10035; CAD_APPROVED: YES; HEIGHT: 0.5; MFG_NAME01: Nexperia; Package Size: DFN1006BD-2; Temp Range: -55  to  +150C
J1 = USB16_TYPEC_4SH_A: CON 2X8 USB2.0_TYPE_C SMT RCPT RA 0.5MM 136H AU --; 3D_Mechanical_Footprint_File: http://fcl.am.freescale.net/ALLEGRO/step/con16_usb_type-c_ra_sm.STEP; AGILE_PN: TMP-CIP-19519; HEIGHT: 3.46mm; MFG_NAME01: GLOBAL CONNECTOR TECHNOLOGY INC; MFG_PN01: USB4110-GF-A; PRE_APN: 211-10362; Package Type: Surface Mount, Right Angle; ROHS: Yes; Temp Range: -40°C to +85°C
J2 = CONN_1x6_SHLD: CON 1X6 CLICK-MATE SHRD SMD 2MM SP 301H SN; 3D_Mechanical_Footprint_File: http://fcl.am.freescale.net/ALLEGRO/step/con1x6_2p0mm_sm.STEP; AGILE_PN: 211-10139; CAD_APPROVED: Yes; Contact Voltage: 250V AC/DC; HEIGHT: 7.65MM; MFG_NAME01: Molex; MFG_PN01: 5024430670; Package Type: SMD/SMT; ROHS: NULL; Temp Range: -40°C  to +105°C
R1 R54 = RES: RES MF 5.1K 1/16W 1% 0402; AGILE_PN: 470-76474; CAD_APPROVED: Yes; FPLIST: RC0402_25,RC0402_HD,0402_CC; HEIGHT: 0.4; MFG_NAME01: THYE MING TECH CO LTD; MFG_PN01: CR02FL6--5K1; ROHS: Yes; Tolerance: 1%
R6 = RES: RES MF 300 OHM 1/10W 5% 0603; AGILE_PN: 470-75842; CAD_APPROVED: Yes; FPLIST: RC0603_OV,RC0603,0603_CC; HEIGHT: 0.55; MFG_NAME01: BOURNS; MFG_PN01: CR0603-JW-301ELF; ROHS: Yes; Tolerance: 5%
TP15 TP16 = TEST_POINT: TEST POINT PAD OBLONG 2MMX1.5MM SMT, NO PART TO ORDER; AGILE_PN: 211-79312; CAD_APPROVED: Yes; HEIGHT: 0.1; MFG_NAME01: N/A; MFG_PN01: N/A; ROHS: Yes
U2 = TPS70950Q_WSON6: IC VREG LDO 3.3V 1A 1.45-5.5V WSON6; 3D_Mechanical_Footprint_File: http://fcl.am.freescale.net/ALLEGRO/step/wson6_0p65_2p1x2p1.STEP; AGILE_PN: 315-10186; CAD_APPROVED: Yes; HEIGHT: 0.8; MFG_NAME01: Texas Instruments; ROHS: NULL; Temp Range: -40C to +125C
U3 = IMX6_BGA_196P: IC CPU ARM CORTEX-M7 600MHZ 1.3V MAPBGA196; 3D_Mechanical_Footprint_File: http://fcl.am.freescale.net/ALLEGRO/step/bga196_0p8_12x12mm_a.step; AGILE_PN: 312-10172; CAD_APPROVED: Yes; HEIGHT: 1.52; MFG_NAME01: NXP SEMICONDUCTOR; ROHS: NULL; Supply Voltage: 1.3 V; Temp Range: 0°C ~ 95°C; VOLTAGE: 1.3V
U13 = NX5P3290_16P: IC SW PWR CURRENT LIMITER ADJ 0.4-3.3A 4-5.5V WLCSP16; 3D_Mechanical_Footprint_File: http://fcl.am.freescale.net/ALLEGRO/step/bga16_0p5_2p23x2p23.step; AGILE_PN: 315-82308; CAD_APPROVED: Yes; HEIGHT: 0.595; MFG_NAME01: NXP SEMICONDUCTOR; ROHS: Yes; Temp Range: -40°C ~ 85°C; VOLTAGE: 4-5.5V
U19 = NCP151_4P-EP: IC LIN VREG LDO 3.3V/1.8V 300mA 1.7-5.5V XDFN4; 3D_Mechanical_Footprint_File: http://fcl.am.freescale.net/ALLEGRO/step/dfn1010-4_epad0p4.STEP; AGILE_PN: 315-10236; CAD_APPROVED: Yes; HEIGHT: 0.43mm; MFG_NAME01: ON SEMICONDUCTOR; Package Size: 1 x 1 mm; ROHS: NULL; Temp Range: -40°C to 85°C

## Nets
1V8: C58.1 C114.1 U6.C1(VDD) U19.3(OUT2)
3V3: C8.1 C54.1 C55.1 C56.1 C59.1 C60.1 C61.1 C62.1 C63.1 C64.1 C65.1 C89.1 C90.1 C95.1 C96.1 C97.1 C98.1 C99.1 C100.1 C105.1 C106.1 C110.1 C111.1 C117.1 C118.1 C124.1 C125.1 C128.1 C131.1 CN1.4(VDD) D10.A J4.8 L3.1 L4.1 L5.2 L7.2 R2.2 R3.2 R4.1 R13.2 R14.2 R15.1 R16.1 R18.2 R22.2 R27.2 R28.2 R55.1 R63.2 SW2.1(COMMON) TP3.1(Pin1) U2.1(OUT) U3.E6(NVCC_EMC_1) U3.E9(NVCC_GPIO_1) U3.F5(NVCC_EMC_2) U3.F10(NVCC_GPIO_2) U3.J6(NVCC_SD0) U3.J10(NVCC_GPIO_3) U3.K5(NVCC_SD1) U3.N14(VDDA_ADC_3P3) U3.P12(VDD_HIGH_IN) U6.B3(VDDIO) U7.5(VDDIO) U7.8(VDD) U8.1(VDDIO) U8.6(CSB) U8.10(VDD) U9.3(VDD) U9.11(VDDIO) U10.2 U10.4 U10.6 U16.5(VIO) U17.3(VCC)
3V3_SNVS: C137.1 D2.1(A1) D4.A TP14.1(Pin1) U19.1(OUT1)
5V: C6.1 C15.1 C116.1 C130.1 C135.1 D6.A D113.2(C2) F1.1 F2.1 FL1.1(INPUT) FL2.1(INPUT) FL3.1(INPUT) FL4.1(INPUT) FL7.1(INPUT) FL8.1(INPUT) J2.1 J2.2 R50.1 U13.C2(VBUS3) U13.D1(VBUS1) U13.D2(VBUS2) U16.3(VCC)
GND: C3.2 C6.2 C8.2 C13.2 C15.2 C26.2 C28.2 C37.2 C38.2 C39.2 C40.2 C41.2 C42.2 C43.2 C44.2 C45.2 C46.2 C47.2 C48.2 C49.2 C50.2 C53.2 C54.2 C55.2 C56.2 C57.2 C58.2 C59.2 C60.2 C61.2 C62.2 C63.2 C64.2 C65.2 C66.2 C67.2 C68.2 C69.2 C70.2 C71.2 C72.2 C73.2 C74.2 C77.2 C79.2 C80.2 C81.2 C83.2 C84.2 C85.2 C86.2 C89.2 C90.2 C91.2 C92.2 C93.2 C95.2 C96.2 C97.2 C98.2 C99.2 C100.2 C105.2 C106.2 C110.2 C111.2 C114.2 C116.2 C117.2 C118.2 C119.2 C124.2 C125.2 C126.2 C127.2 C128.2 C129.2 C130.2 C131.2 C133.2 C134.2 C135.2 C136.2 C137.2 C138.2 CN1.6(VSS) CN1.10(CD_COMMON) D7.3(COM_CATHODE) D8.C(CATHODE) D9.C(CATHODE) D107.3(ANODES) D112.1(C1) D113.1(C1) D114.1(C1) FL1.2(GND) FL2.2(GND) FL3.2(GND) FL4.2(GND) FL5.2(GND) FL7.2(GND) FL8.2(GND) J1.A1B12(GND1) J1.B1A12(GND2) J1.SH1 J1.SH2 J1.SH3 J1.SH4 J2.5 J2.6 J2.SH1 J2.SH2 J3.10 J3.S1 J3.S2 J4.10 J4.SH1 J4.SH2 J5.4 J5.SH1 J5.SH2 J6.8 J6.SH1 J6.SH2 J7.6 J7.SH1 J7.SH2 J8.6 J8.SH1 J8.SH2 J9.6 J9.SH1 J9.SH2 J10.4 J10.SH1 J10.SH2 J11.4 J11.SH1 J11.SH2 J12.2 J12.3 J13.2 J13.3 P1.S1 P1.S2 Q1.2(SOURCE) R1.1 R8.1 R19.2 R25.2 R26.2 R33.2 R48.2 R51.2 R53.1 R54.2 R59.2 R60.1 TP16.1 U2.3(GND) U2.7(EPAD) U3.A1(VSS1) U3.A14(VSS2) U3.B5(VSS3) U3.B10(VSS4) U3.E2(VSS5) U3.E13(VSS6) U3.G7(VSS7) U3.G8(VSS8) U3.H7(VSS9) U3.H8(VSS10) U3.J7(VSS11) U3.J8(VSS12) U3.K2(VSS13) U3.K6(TEST_MODE) U3.K9(NGND_KEL0) U3.K13(VSS14) U3.L9(VSS15) U3.N1(DCDC_GND_1) U3.N2(DCDC_GND_2) U3.N5(VSS16) U3.N8(VSS17) U3.P1(VSS18) U3.P14(VSS19) U5.6(XI/CLK_IN) U5.37(GNDPAD) U6.B1(GND) U6.B2(ADSEL) U6.C3(BYPASS) U7.6(GND) U8.3(VSS_1) U8.5(SDO) U8.8(VSS_2) U8.9(VSS_3) U9.4(GNDA) U9.6(GNDIO) U9.7(PS) U13.B3(GND1) U13.C3(GND2) U13.D3(GND3) U16.2(GND) U16.9(E_PAD) U17.1(GND) U19.2(GND) U19.5(EP) Y1.2 Y1.4
P3V3_ENET_VIO: C44.1 C45.1 C46.1 C47.1 L5.1 U5.22(VDDIO_1) U5.27(VDDIO_3) U5.35(VDDIO_2)
VBAT: D2.2(A2) R6.2 TP15.1
VBUS: C134.1 J1.A4B9(VBUS1) J1.A8(SBU1) J1.B4A9(VBUS2) J1.B8(SBU2) R49.1 U3.N6(USB_OTG1_VBUS) U13.A1(VIN1) U13.A2(VIN2)
VDD_HIGH_CAP: C72.1 C127.1 U3.P8(VDD_HIGH_CAP)
VDD_SNVS_CAP: C73.1 U3.M10(VDD_SNVS_CAP)
VDD_SNVS_IN: C77.1 D2.3(C) R47.1 U3.M9(VDD_SNVS_IN)
VDD_SOC_IN: C13.1 C67.1 C68.1 C69.1 C70.1 C71.1 C136.1 L9.2 U3.F6(VDD_SOC_IN_1) U3.F7(VDD_SOC_IN_2) U3.F8(VDD_SOC_IN_3) U3.F9(VDD_SOC_IN_4) U3.G6(VDD_SOC_IN_5) U3.G9(VDD_SOC_IN_6) U3.H6(VDD_SOC_IN_7) U3.H9(VDD_SOC_IN_8) U3.J5(DCDC_SENSE) U3.J9(VDD_SOC_IN_9)
ADC_5V: R50.2 R51.1 U3.H13(GPIO_AD_B1_08)
ARM: R42.1 U3.C10(GPIO_B0_12)
AUX_CTS: RN5.3(PIN3) U3.L10(GPIO_AD_B0_15)
AUX_RTS: RN5.4(PIN4) U3.H14(GPIO_AD_B0_14)
AUX_RX: RN5.2(PIN2) U3.B11(GPIO_B1_01)
AUX_TX: RN5.1(PIN1) U3.A11(GPIO_B1_00)
BARO_MAG_SCL: R28.1 U3.K14(GPIO_AD_B0_12) U6.A3(SCK) U8.2(SCK)
BARO_MAG_SDA: R27.1 U3.L14(GPIO_AD_B0_13) U6.A2(SDA) U8.4(SDI)
BMI088_DRDY1: U3.M13(GPIO_AD_B1_09) U9.16(INT1)
BMI088_DRDY2: U3.D9(GPIO_B0_10) U9.1(INT2)
BMM350_INT: U3.E1(GPIO_EMC_29) U6.A1(INT)
BMP390_INT: U3.C6(GPIO_EMC_30) U8.7(INT)
BOOT_MODE_BUTTON: R53.2 SW2.2(NO) U3.F11(GPIO_AD_B0_04)
BUZZER: R31.1 U3.G2(GPIO_EMC_23)
BUZZER_EXT: J4.9 Q1.3(DRAIN)
CAN3_RX: U3.E4(GPIO_EMC_37) U16.4(RXD)
CAN3_TX: U3.C3(GPIO_EMC_36) U16.1(TXD)
CAN_H: D107.1(CATHODE1) J5.2 R9.2 U16.7(CANH)
CAN_L: D107.2(CATHODE2) J5.3 R10.2 U16.6(CANL)
CD_B: CN1.9(CD_SW) R55.2 U3.E5(GPIO_EMC_35)
CONSOLE_RX: J3.3 U3.B3(GPIO_EMC_26)
CONSOLE_TX: J3.2 U3.D2(GPIO_EMC_25)
DCDC_PSWITCH: C138.1 R63.1 U3.K3(DCDC_PSWITCH)
ENET_RMII_REF_CLK: TP11.1(Pin1) U3.B13(GPIO_B1_10) U5.29(TXC)
ETH_DV: U3.C12(GPIO_B1_06) U5.25(RX_CTL/CONFIG6)
ETH_INT: R18.1 U3.E11(GPIO_B0_15) U5.2(~{INT})
ETH_MDC: U3.C14(GPIO_B1_14) U5.1(MDC)
ETH_MDIO: R16.2 U3.B14(GPIO_B1_15) U5.36(MDIO)
ETH_RST: R15.2 U3.E10(GPIO_B0_14) U5.10(~{RST})
ETH_RX_ER: U3.C13(GPIO_B1_11) U5.19(RX_ER/GPIO2/TDO/CONFIG1)
ETH_RXD0: U3.E12(GPIO_B1_04) U5.24(RXD0/CONFIG5)
ETH_RXD1: U3.D12(GPIO_B1_05) U5.23(RXD1/CONFIG4)
ETH_TRX_M: C52.2 D7.2(CATHODE2) P1.1 R20.1
ETH_TRX_P: C51.2 D7.1(CATHODE1) P1.2 R21.1
ETH_TX_EN: U3.A13(GPIO_B1_09) U5.30(TX_CTL)
ETH_TXD0: U3.B12(GPIO_B1_07) U5.31(TXD0)
ETH_TXD1: U3.A12(GPIO_B1_08) U5.32(TXD1)
EXT_SCL: R14.1 R43.1 RN6.3(PIN3) U3.J11(GPIO_AD_B1_00)
EXT_SDA: R13.1 R44.1 RN6.4(PIN4) U3.K11(GPIO_AD_B1_01)
GPANAIO: TP9.1(TP) U3.N10(GPANAIO)
GPIO_SD_B0_00: CN1.3(CMD) U3.J4(GPIO_SD_B0_00)
GPIO_SD_B0_01: CN1.5(CLK) U3.J3(GPIO_SD_B0_01)
GPIO_SD_B0_02: CN1.7(DAT0) U3.J1(GPIO_SD_B0_02)
GPIO_SD_B0_03: CN1.8(DAT1) U3.K1(GPIO_SD_B0_03)
GPIO_SD_B0_04: CN1.1(DAT2) U3.H2(GPIO_SD_B0_04)
GPIO_SD_B0_05: CN1.2(CD/DAT3) U3.J2(GPIO_SD_B0_05)
GPS_LED: R41.1 U3.B7(GPIO_EMC_39)
GPS_RX: RN6.2(PIN2) U3.M12(GPIO_AD_B1_03)
GPS_TX: RN6.1(PIN1) U3.L11(GPIO_AD_B1_02)
ICM42688_DRDY: U3.D5(GPIO_EMC_32) U7.4(INT1/INT)
LED_B: R58.2 U3.D4(GPIO_EMC_34)
LED_G: R57.2 U3.D6(GPIO_EMC_38)
LED_R: R56.2 U3.C4(GPIO_EMC_33)
NVCC_PLL: C74.1 C126.1 U3.P10(NVCC_PLL)
ONE_WIRE: J12.4 J13.4 U3.C5(GPIO_EMC_31)
OSD_CS: J6.5 U3.L3(GPIO_SD_B1_06)
OSD_DRDY: J6.6 U3.P4(GPIO_SD_B1_10)
OSD_MISO: J6.3 U3.N4(GPIO_SD_B1_09)
OSD_MOSI: J6.4 U3.P3(GPIO_SD_B1_08)
OSD_nRESET: J6.7 U3.P5(GPIO_SD_B1_11)
OSD_SCK: J6.2 U3.L4(GPIO_SD_B1_07)
PM_SCL: R2.1 R61.2 U3.F1(GPIO_EMC_22)
PM_SDA: R3.1 R62.2 U3.C1(GPIO_EMC_21)
PMIC_ON_REQ: R4.2 U2.4(EN) U3.K7(PMIC_ON_REQ)
POR_B: C85.1 C119.1 J3.9 R47.2 U3.M7(~{POR}) U17.2(~{RESET})
PWM_1: RN1.1(PIN1) U3.H5(GPIO_EMC_06)
PWM_2: RN1.2(PIN2) U3.H4(GPIO_EMC_07)
PWM_3: RN1.3(PIN3) U3.H3(GPIO_EMC_08)
PWM_4: RN1.4(PIN4) U3.C2(GPIO_EMC_09)
PWM_5: RN7.4(PIN4) U3.F4(GPIO_EMC_02)
PWM_6: RN7.3(PIN3) U3.G4(GPIO_EMC_03)
PWM_7: RN7.2(PIN2) U3.F2(GPIO_EMC_04)
PWM_8: RN7.1(PIN1) U3.G5(GPIO_EMC_05)
RC_RX: R64.1 U3.J13(GPIO_AD_B1_11)
RC_TX: R52.1 U3.L13(GPIO_AD_B1_10)
RTC_XTAL_1: C28.1 U3.N9(RTC_XTALI) Y2.1
RTC_XTAL_2: C84.1 U3.P9(RTC_XTALO) Y2.2
SPI1_CS: U3.D7(GPIO_B0_00) U9.14(CSB1)
SPI1_CS2: U3.C11(GPIO_B1_02) U9.5(CSB2)
SPI1_MISO: U3.E7(GPIO_B0_01) U9.10(SDO2) U9.15(SDO1)
SPI1_MOSI: U3.E8(GPIO_B0_02) U9.9(SDI/SDA)
SPI1_SCK: U3.D8(GPIO_B0_03) U9.8(SCK/SCL)
SPI2_CS: U3.H12(GPIO_AD_B1_12) U7.12(AP_CS)
SPI2_MISO: U3.H11(GPIO_AD_B1_13) U7.1(AP_SDO/AP_AD0)
SPI2_MOSI: U3.G12(GPIO_AD_B1_14) U7.14(AP_SDA/AP_SDIO/AP_SDI)
SPI2_SCK: U3.J14(GPIO_AD_B1_15) U7.13(AP_SCL/AP_SCLK)
SWDCLK: J3.5 U3.F12(GPIO_AD_B0_07)
SWDIO: J3.4 U3.E14(GPIO_AD_B0_06)
SWO: J3.6 U3.D10(GPIO_B0_13)
TELEM2_CTS: RN4.2(PIN2) U3.D1(GPIO_EMC_28)
TELEM2_RTS: RN4.1(PIN1) U3.A2(GPIO_EMC_27)
TELEM2_RX: RN4.3(PIN3) U3.D14(GPIO_B1_13)
TELEM2_TX: RN4.4(PIN4) U3.D13(GPIO_B1_12)
TELEM_CTS: RN3.3(PIN3) U3.L12(GPIO_AD_B1_04)
TELEM_RTS: RN3.4(PIN4) U3.K12(GPIO_AD_B1_05)
TELEM_RX: RN3.2(PIN2) U3.K10(GPIO_AD_B1_07)
TELEM_TX: RN3.1(PIN1) U3.J12(GPIO_AD_B1_06)
TRX_FL_N: C52.1 FL6.4
TRX_FL_P: C51.1 FL6.3
TRX_N: FL6.1 U5.15(TRX_M)
TRX_P: FL6.2 U5.14(TRX_P)
USB_DN: D112.2(C2) J1.A7(DN1) J1.B7(DN2) U3.M8(USB_OTG1_DN)
USB_DP: D114.2(C2) J1.A6(DP1) J1.B6(DP2) U3.L8(USB_OTG1_DP)
USB_OTG2_VBUS: U3.P6(USB_OTG2_VBUS)
VREGA_IN: C37.1 C38.1 C39.1 L3.2 U5.7(VREGA_IN) U5.9(VDDA_AO)
VREGA_OUT: C40.1 C41.1 C50.1 U5.8(VREGA_OUT) U5.13(VDDA_TRX_1) U5.16(VDDA_TRX_2)
XTAL_1: C26.1 R8.2 U3.P11(XTALI) Y1.1
XTAL_2: C66.1 U3.N11(XTALO) Y1.3
N50608: C42.1 C43.1 L4.2 U5.4(VREGD_IN)
N50874: C48.1 C49.1 U5.3(VDD_CORE)
N51338: R19.1 U5.11(WAKE_IN_OUT)
N51478: R23.1 U5.17(TMS/_GPIO0/CONFIG0)
N51550: R24.1 U5.18(TDI/GPIO1)
N51666: R25.1 U5.28(TX_ER/GPIO9/TCK)
N51920: R22.1 U5.21(RXD2/GPIO4/CONFIG3)
N51964: C53.1 R20.2 R21.2 R26.1
N52100: D8.A(ANODE) R23.2
N52104: D9.A(ANODE) R24.2
N126903: FL2.3(OUTPUT) J7.1
N128069: D6.C FL5.1(INPUT)
N128073: FL5.3(OUTPUT) J10.1
N128314: FL1.3(OUTPUT) J5.1
N170982: D4.C R6.1
N461764: C57.1 U6.C2(CRST)
N482457: J2.3 R61.1
N482469: J2.4 R62.1
N505782: J7.5 RN5.5(PIN5)
N508537: FL3.3(OUTPUT) J8.1
N508653: J8.2 RN3.8(PIN8)
N508691: J8.3 RN3.7(PIN7)
N508699: J8.4 RN3.6(PIN6)
N508753: J8.5 RN3.5(PIN5)
N509562: FL4.3(OUTPUT) J9.1
N509632: J9.2 RN4.5(PIN5)
N509670: J9.3 RN4.6(PIN6)
N509708: J9.4 RN4.7(PIN7)
N509720: J9.5 RN4.8(PIN8)
N519858: J7.2 RN5.8(PIN8)
N519864: J7.3 RN5.7(PIN7)
N519870: J7.4 RN5.6(PIN6)
N523855: FL7.3(OUTPUT) J4.1
N524682: J4.6 R42.2
N525355: J10.2 R43.2
N525427: J10.3 R44.2
N539480: D10.C J3.1
N555976: C3.1 C133.1 L8.2 U2.6(IN) U19.4(IN)
N598432: C81.1 C83.1 C92.1 C93.1 L7.1 U3.K4(DCDC_IN_Q) U3.L1(DCDC_IN_1) U3.L2(DCDC_IN_2)
N598654: L9.1 U3.M1(DCDC_LP_1) U3.M2(DCDC_LP_2)
N642052: C79.1 C80.1 U3.K8(VDD_USB_CAP)
N684610: Q1.1(GATE) R31.2 R33.1
N691592: R60.2 U16.8(STB)
N694575: C129.1 R9.1 R10.1
N698651: J4.2 RN6.8(PIN8)
N698657: J4.3 RN6.7(PIN7)
N698663: J4.5 RN6.5(PIN5)
N698669: J4.4 RN6.6(PIN6)
N702971: R59.1 U3.G14(GPIO_AD_B0_05)
N712262: J4.7 R41.2
N735138: C91.1 D106.C J11.1
N872857: F1.2 L8.1
N872970: D106.A F2.2
N16793807: J11.2 R52.2
N16793810: J11.3 R64.2
N16795144: J13.5 RN1.8(PIN8)
N16795147: J13.6 RN1.7(PIN7)
N16795150: J13.7 RN1.6(PIN6)
N16795153: J13.8 RN1.5(PIN5)
N16796284: J12.5 RN7.5(PIN5)
N16796293: J12.6 RN7.6(PIN6)
N16796302: J12.7 RN7.7(PIN7)
N16796306: J12.8 RN7.8(PIN8)
N16797707: FL8.3(OUTPUT) J6.1
N16835418: TP17.1(Pin1) U7.7(RESV3)
N16835525: TP18.1(Pin1) U7.11(RESV5/AUX1_SDO)
N16852787: R48.1 U13.A3(ILIM)
N16852805: R49.2 U13.B4(EN)
N16852807: C86.1 U13.D4(CAP)
N16859737: J1.B5(CC2) R54.1
N16859747: J1.A5(CC1) R1.2
N16864636: R58.1 U10.1
N16864665: R56.1 U10.3
N16864695: R57.1 U10.5

Not connected (* = marked no-connect by the designer): J3 7* 8*; J12 1*; J13 1*; U2 2(NC1)* 5(NC2)*; U3 A3(GPIO_EMC_20)* A4(GPIO_EMC_17)* A5(GPIO_EMC_16)* A6(GPIO_EMC_13)* A7(GPIO_EMC_40)* A8(GPIO_B0_06)* A9(GPIO_B0_07)* A10(GPIO_B0_11)* B1(GPIO_EMC_15)* B2(GPIO_EMC_18)* B4(GPIO_EMC_19)* B6(GPIO_EMC_14)* B8(GPIO_B0_05)* B9(GPIO_B0_08)* C7(GPIO_EMC_41)* C8(GPIO_B0_04)* C9(GPIO_B0_09)* D3(GPIO_EMC_24)* D11(GPIO_B1_03)* E3(GPIO_EMC_00)* F3(GPIO_EMC_01)* F13(GPIO_AD_B0_08)* F14(GPIO_AD_B0_09)* G1(GPIO_EMC_10)* G3(GPIO_EMC_11)* G10(GPIO_AD_B0_11)* G11(GPIO_AD_B0_03)* G13(GPIO_AD_B0_10)* H1(GPIO_EMC_12)* H10(GPIO_AD_B0_01)* L5(GPIO_SD_B1_00)* L6(WAKEUP)* L7(PMIC_STBY_REQ)* M3(GPIO_SD_B1_02)* M4(GPIO_SD_B1_03)* M5(GPIO_SD_B1_01)* M6(ONOFF)* M11(GPIO_AD_B0_02)* M14(GPIO_AD_B0_00)* N3(GPIO_SD_B1_05)* N7(USB_OTG2_DN)* N12(~{USB_OTG1_CHD})* N13(CCM_CLK1_P)* P2(GPIO_SD_B1_04)* P7(USB_OTG2_DP)* P13(CCM_CLK1_N)*; U5 5(XO)* 12(INH)* 20(RXD3/GPIO3/CONFIG2)* 26(RXC/GPIO8/TX_TCLK)* 33(TXD2/GPIO10)* 34(TXD3/GPIO11)*; U7 2(RESV1/AUX1_SDIO/AUX1_SDI/MAS_DA)* 3(RESV2/AUX1_SCLK/MAS_CLK)* 9(INT2/FSYNC/CLKIN)* 10(RESV4/AUX1_CS)*; U9 2(NC)* 12(INT3)* 13(INT4)*; U13 A4(~{FLT})* B1(VCP1)* B2(VCP2)* C1(VCP3)* C4(FO)*

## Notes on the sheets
sheet 1
- REVISION HISTORY
- TABLE OF CONTENTS
- REVISION
- DESCRIPTION OF CHANGE
- DATE
- Approved
- A
- Release of Final Schematic
- 10/22/2024
- Iain Galloway
- Table of Contents
- 1
- COVER PAGE
- A1
- Changed BT1 to DNP, Li-Ion batteries cannot be shipped with baords.
- 10/22/2025
- Iain Galloway
- 2
- POWER DELIVERY
- Completely removed BT1 from shcematic.  Li-Ion batteries soldered or loose
  cannot be shipped with NXP boards.
- B
- 10/22/2025
- Iain Galloway
- 3
- I.MXRT1064_GPIO
- 4
- CONNECTORS_COMMUNICATION
- 5
- ETHERNET
- C
- Several changes made to schematic per document PCML-94468_C.xlsx.
  New USB Connector J1 added.  USB Conn changed to Full SMT.
- 1/22/2025
- Iain Galloway
- 6
- IMU
- 7
- LED
- X-MR-VMU-TROPIC
- SILKSCREEN
- Silkscreen text is this COLOR in the schematic.
- CAD NOTES:
- CAD Notes are this COLOR in the schematic.
sheet 2
- USB TYPE-C
- FILTERING
- CAD:  Please make sure there is adequate thermal relief for this USB connector and U13.
- CAD:  Please make sure there is adequate thermal relief for this USB connector and U13..
- RTC BATTERY CIRCUIT
- 3V3 POWER & 1V8 POWER
- SE BATTERY BACKUP
  SOLDER PADS LOCATED ON PCB
- POWER PORTION OF I.MX1064
- Place 0.22uF next to F6 & F7, 0.22uF next to F8 & F9 and so on.
- Place decaps with the lowest value closer to the IC and the Largest after the closest value
sheet 3
- POWER AND CLOCKS
- CHIP TO GPIO
- Place decaps with the lowest value closer to the IC and the Largest after the closest value
- SD MEMORY CARD
sheet 4
- DEBUG
- PWM
- TELEM 1 & 2
- BM06B-GHS-TBT
- AUX
- CAN & CAN TRANSCEIVER
- BM06B-GHS-TBT
- GPS
- 120 ohm Diff Pair
- I2C
- RC-ELRS
sheet 5
- ETHERNET 100BASE-T1
- DIFF. PAIR
- DIFF. PAIR
- 100 Ohms impedance
- DIFF. PAIR
- LAYOUT NOTE: low
  impedance connection
  to this pin (either
  directly placed or
  connected via Power
  island)
- PHYAD = 18
- Move D8, D9 LED to top side of PCB.
sheet 6
- Accelerometer, Gyroscope, 6-Axis Sensor Output
- MAGNETOMETER
- Make sure C54 is
  placed close to U7, Pin 5.
- I2C Address 0x14h
- Make sure C55,C56 are
  placed close to U7, Pin 8.
- 6-Axis Motion Tracking (IMU)
- Pressure Sensor
- Gyroscope
- I2C Address 0X76
sheet 7
- LED
- SPI (OSD)
